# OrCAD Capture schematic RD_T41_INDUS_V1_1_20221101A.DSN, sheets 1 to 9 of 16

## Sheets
1 PAGE10_SLCD_BT656: size A3; title: RD_T41QFN_INDUS; rev: 1.1; note: SLCD_BT656
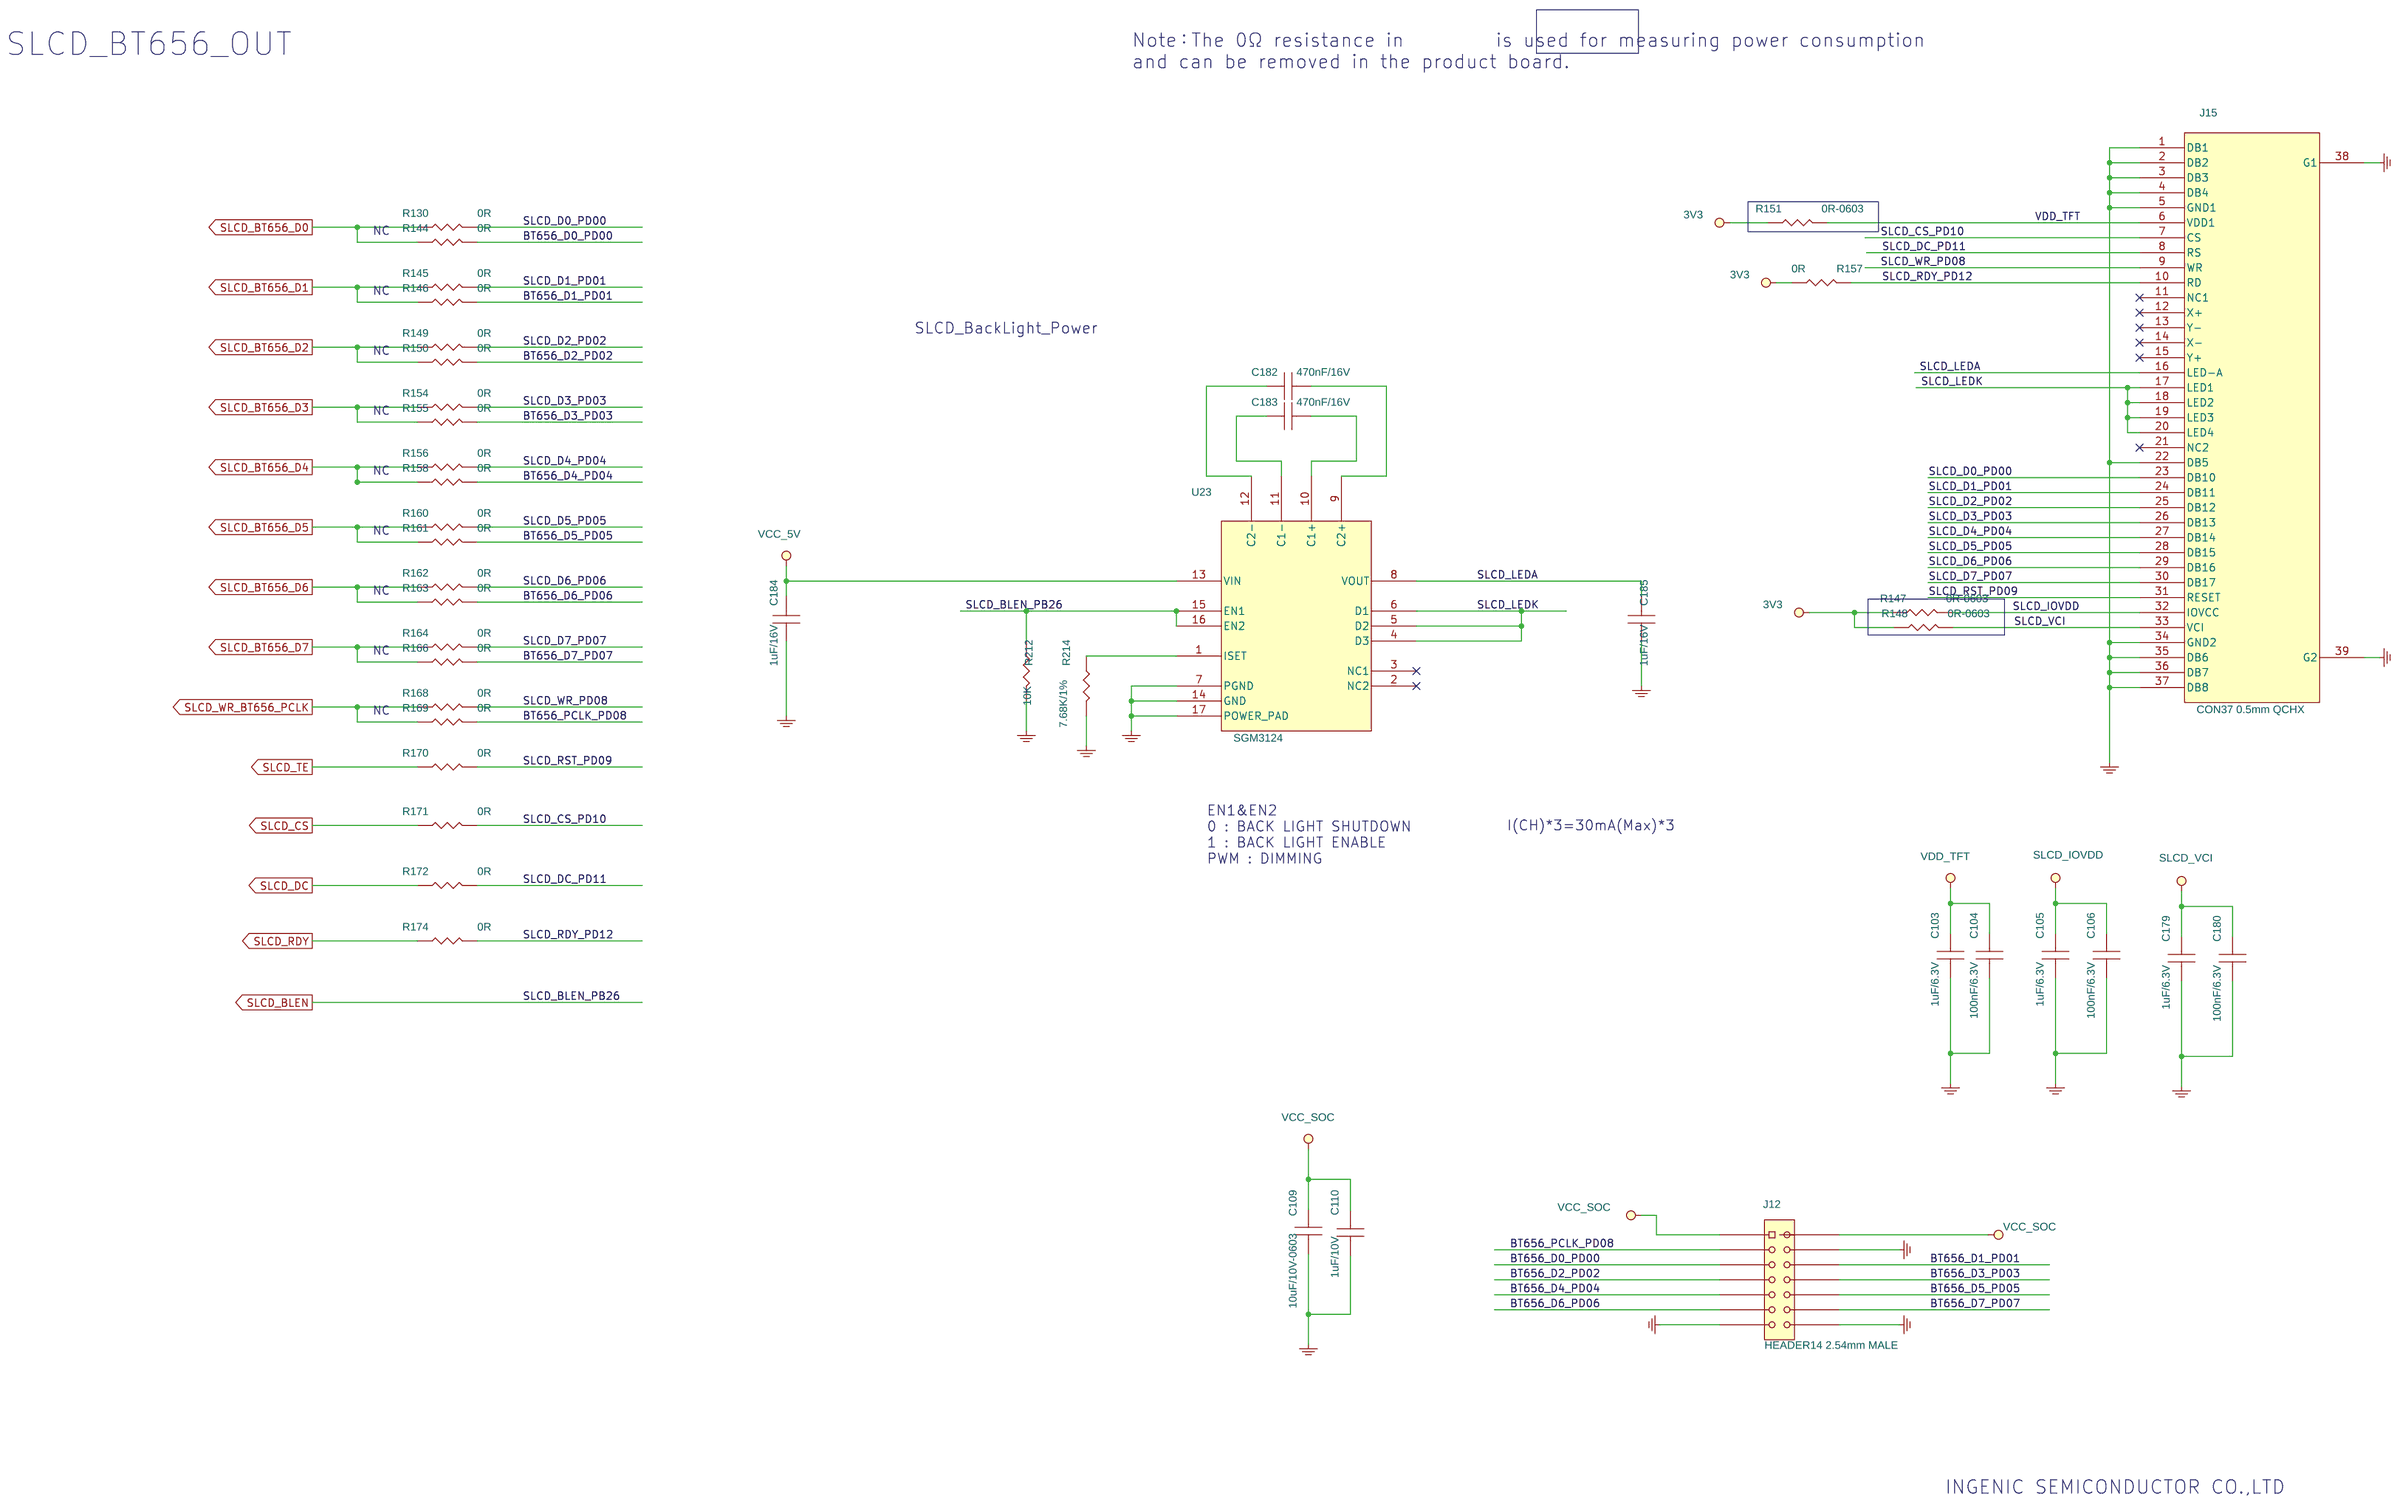
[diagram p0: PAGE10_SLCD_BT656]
2 PAGE13_ETH_PHY: size A3; note: ETH_PHY
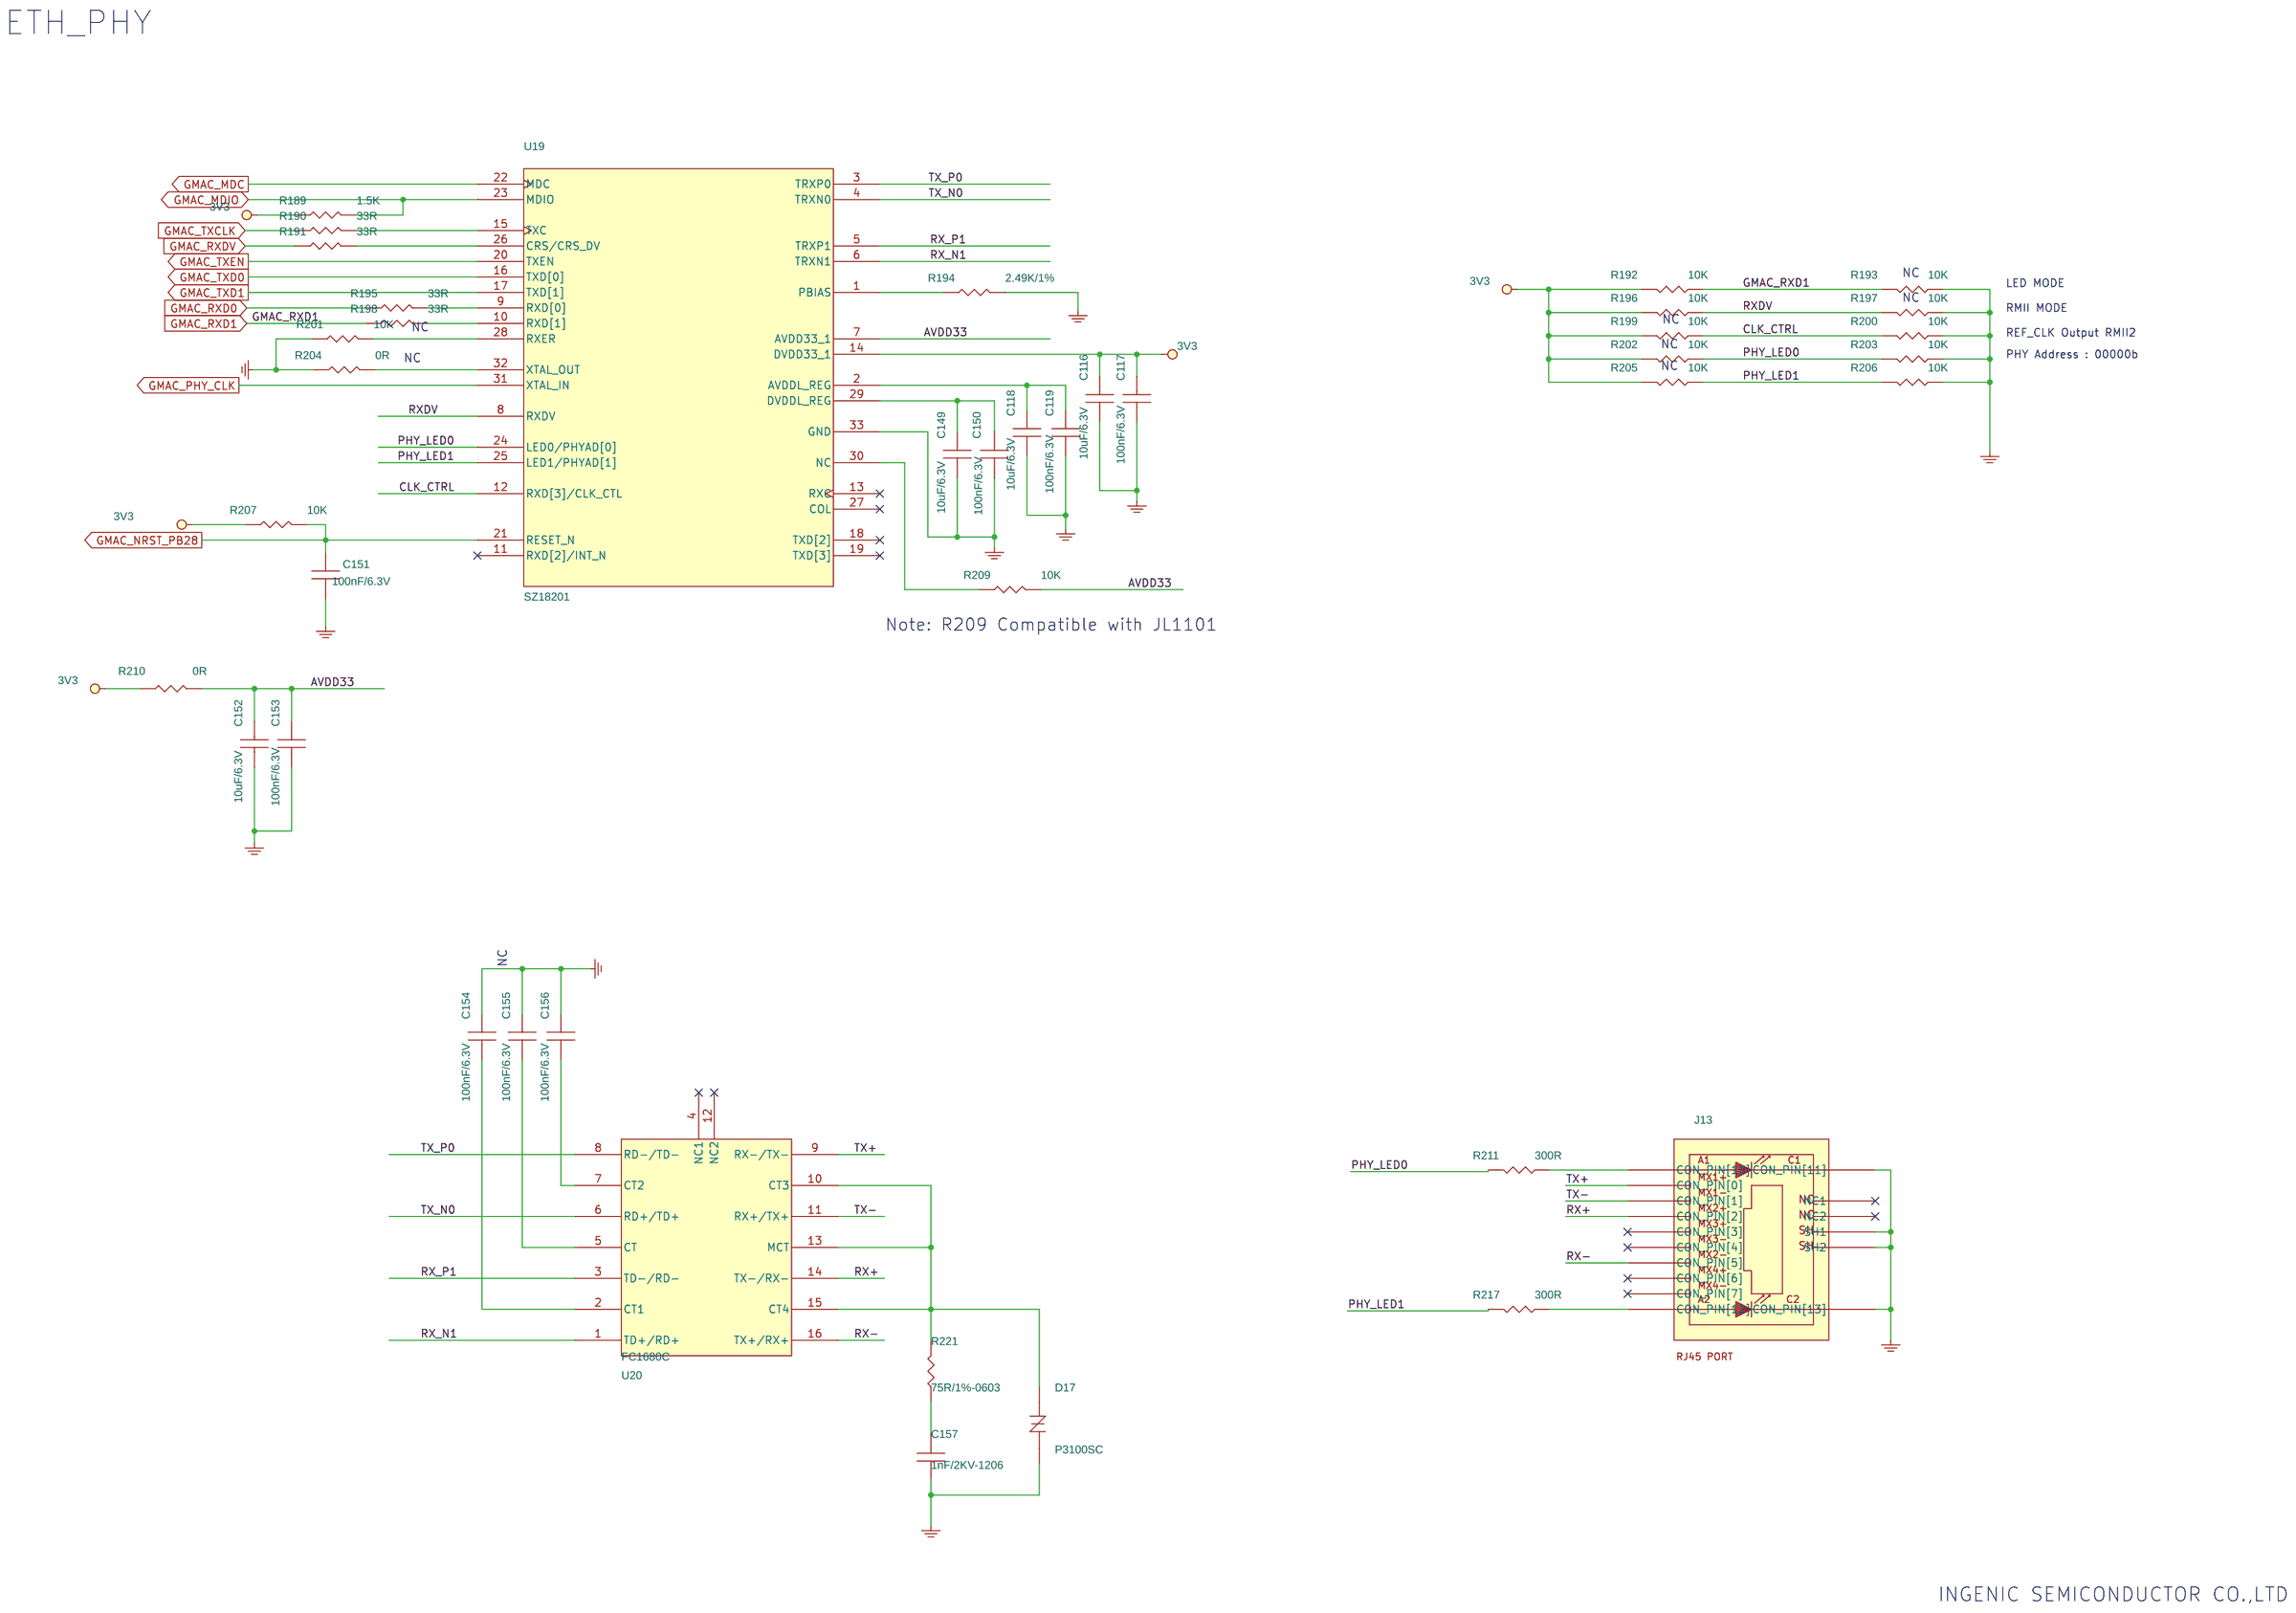
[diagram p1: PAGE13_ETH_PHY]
3 PAGE12_WIFI_MOUDLE: size A3; note: WIFI_ATBM6441
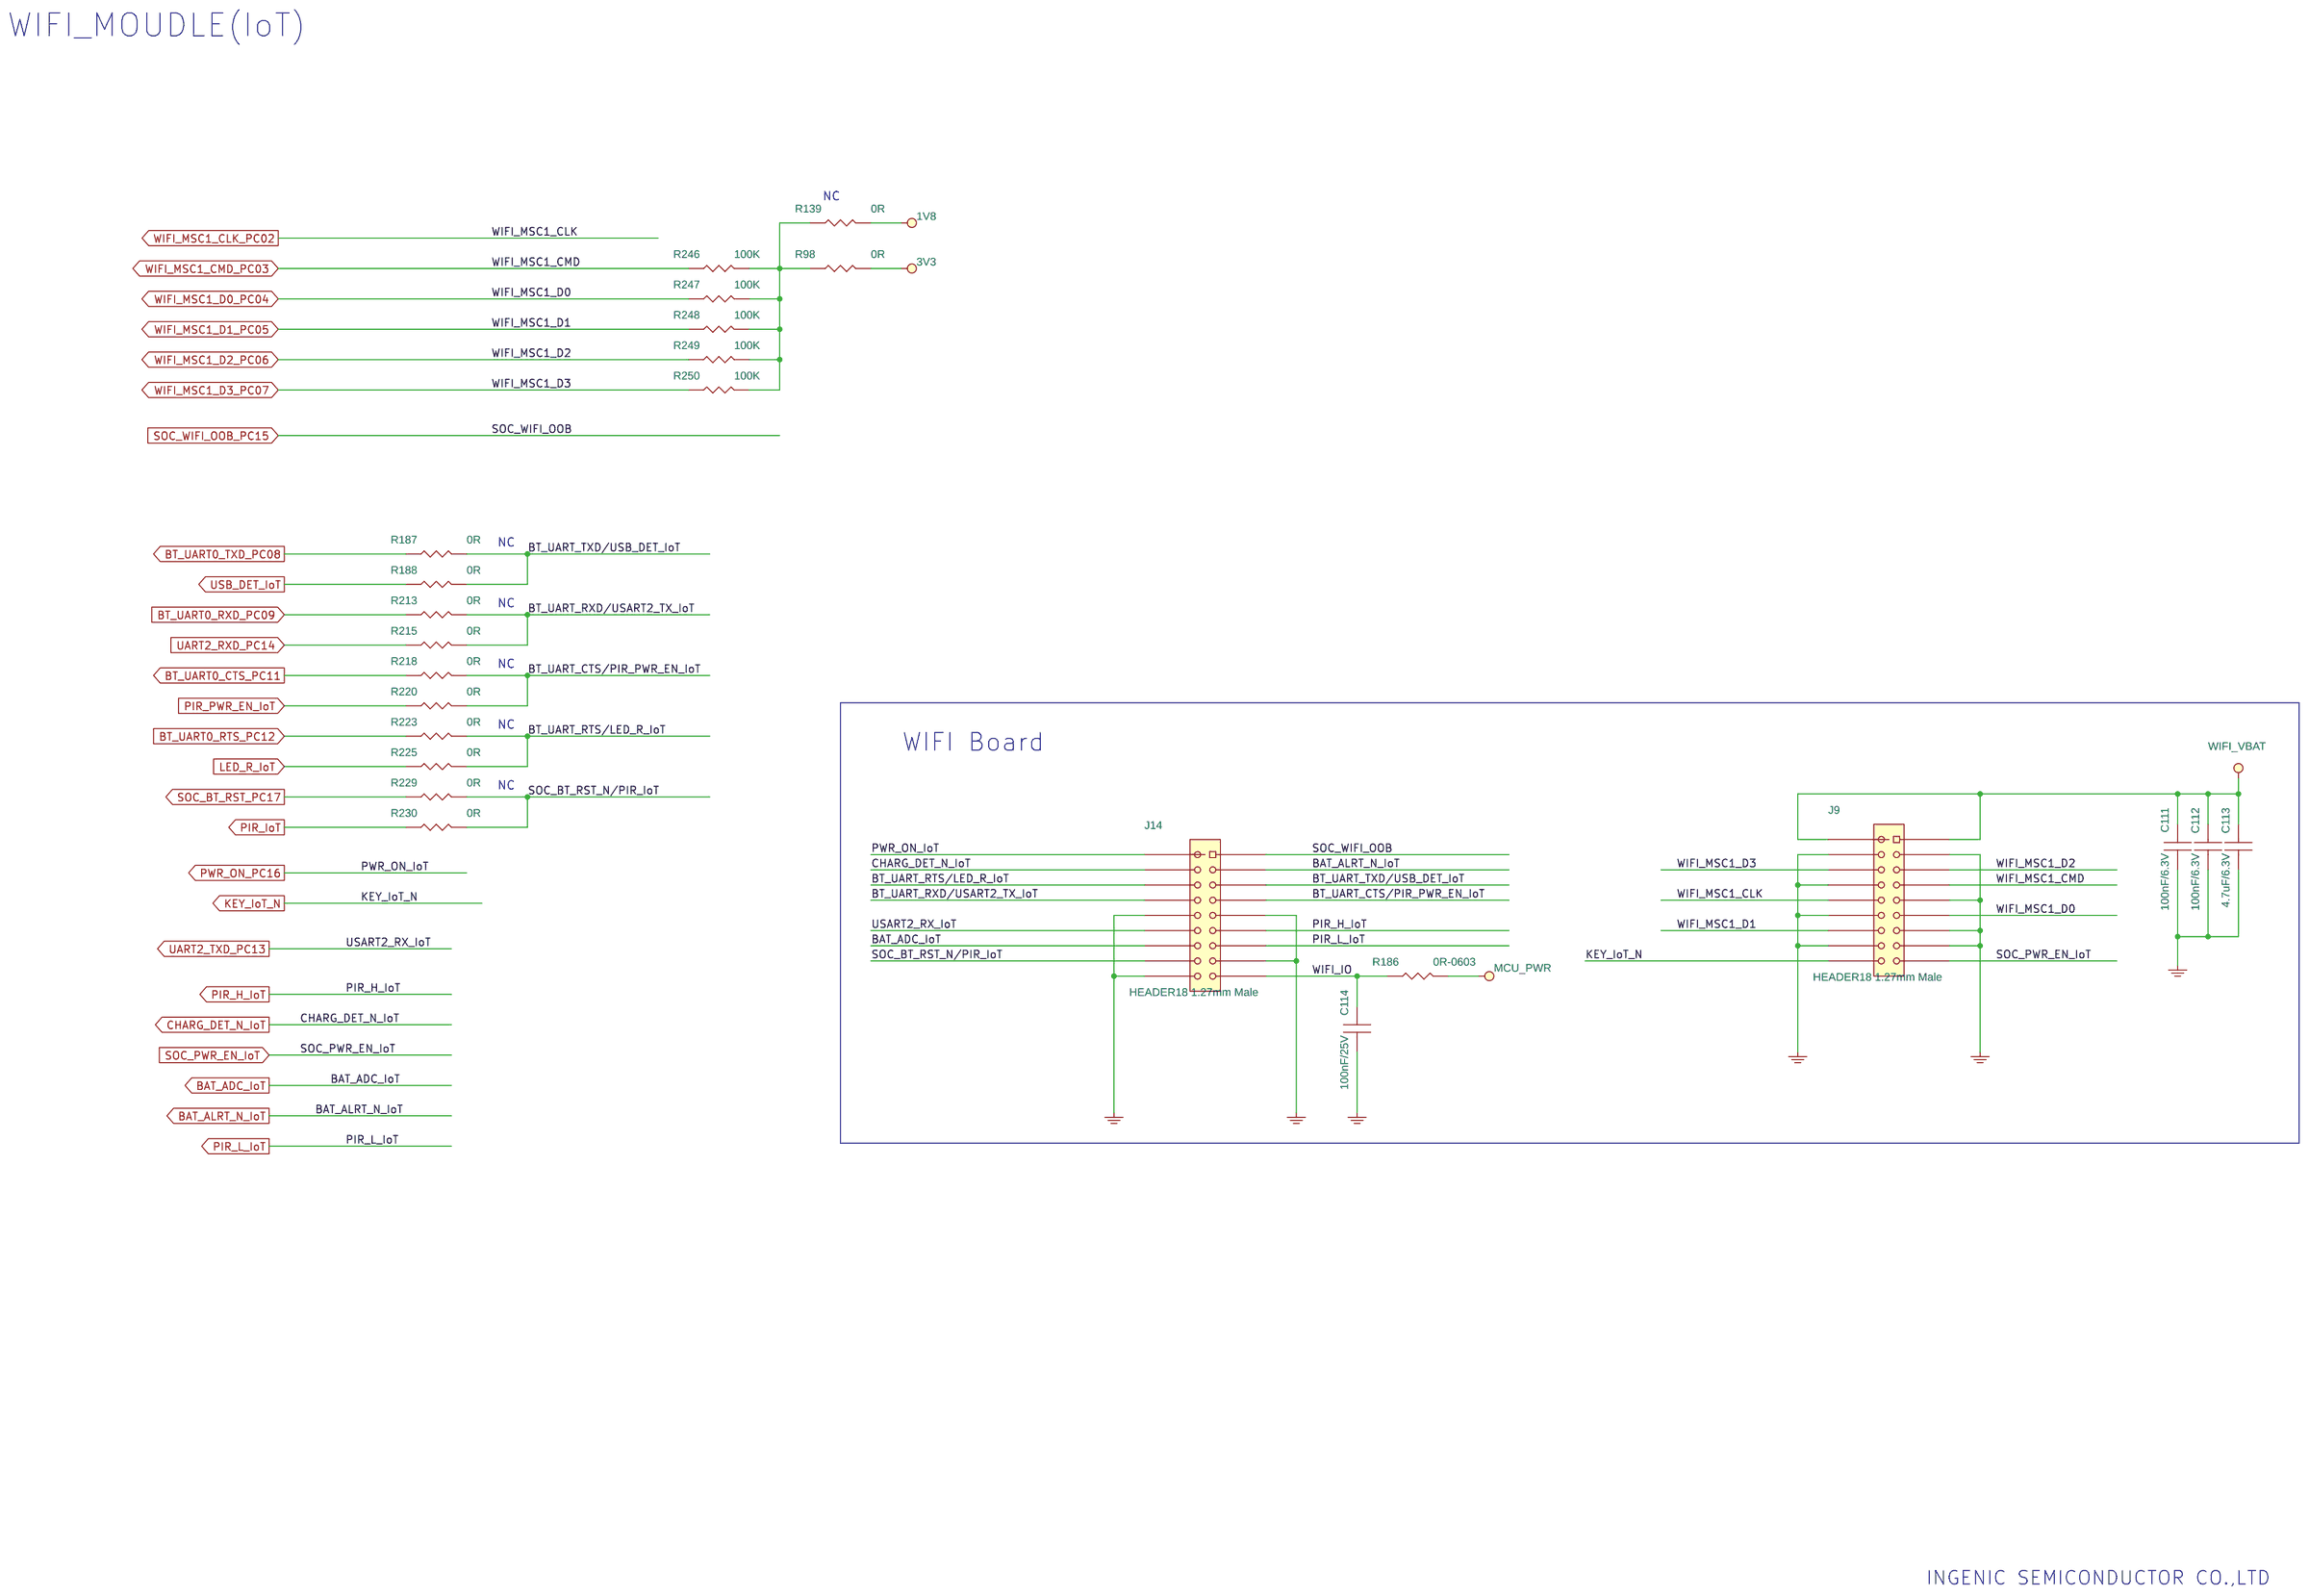
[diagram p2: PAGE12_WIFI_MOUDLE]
4 PAGE08_T41_INTERFACE02: size A3; note: T41_INTERFACE02
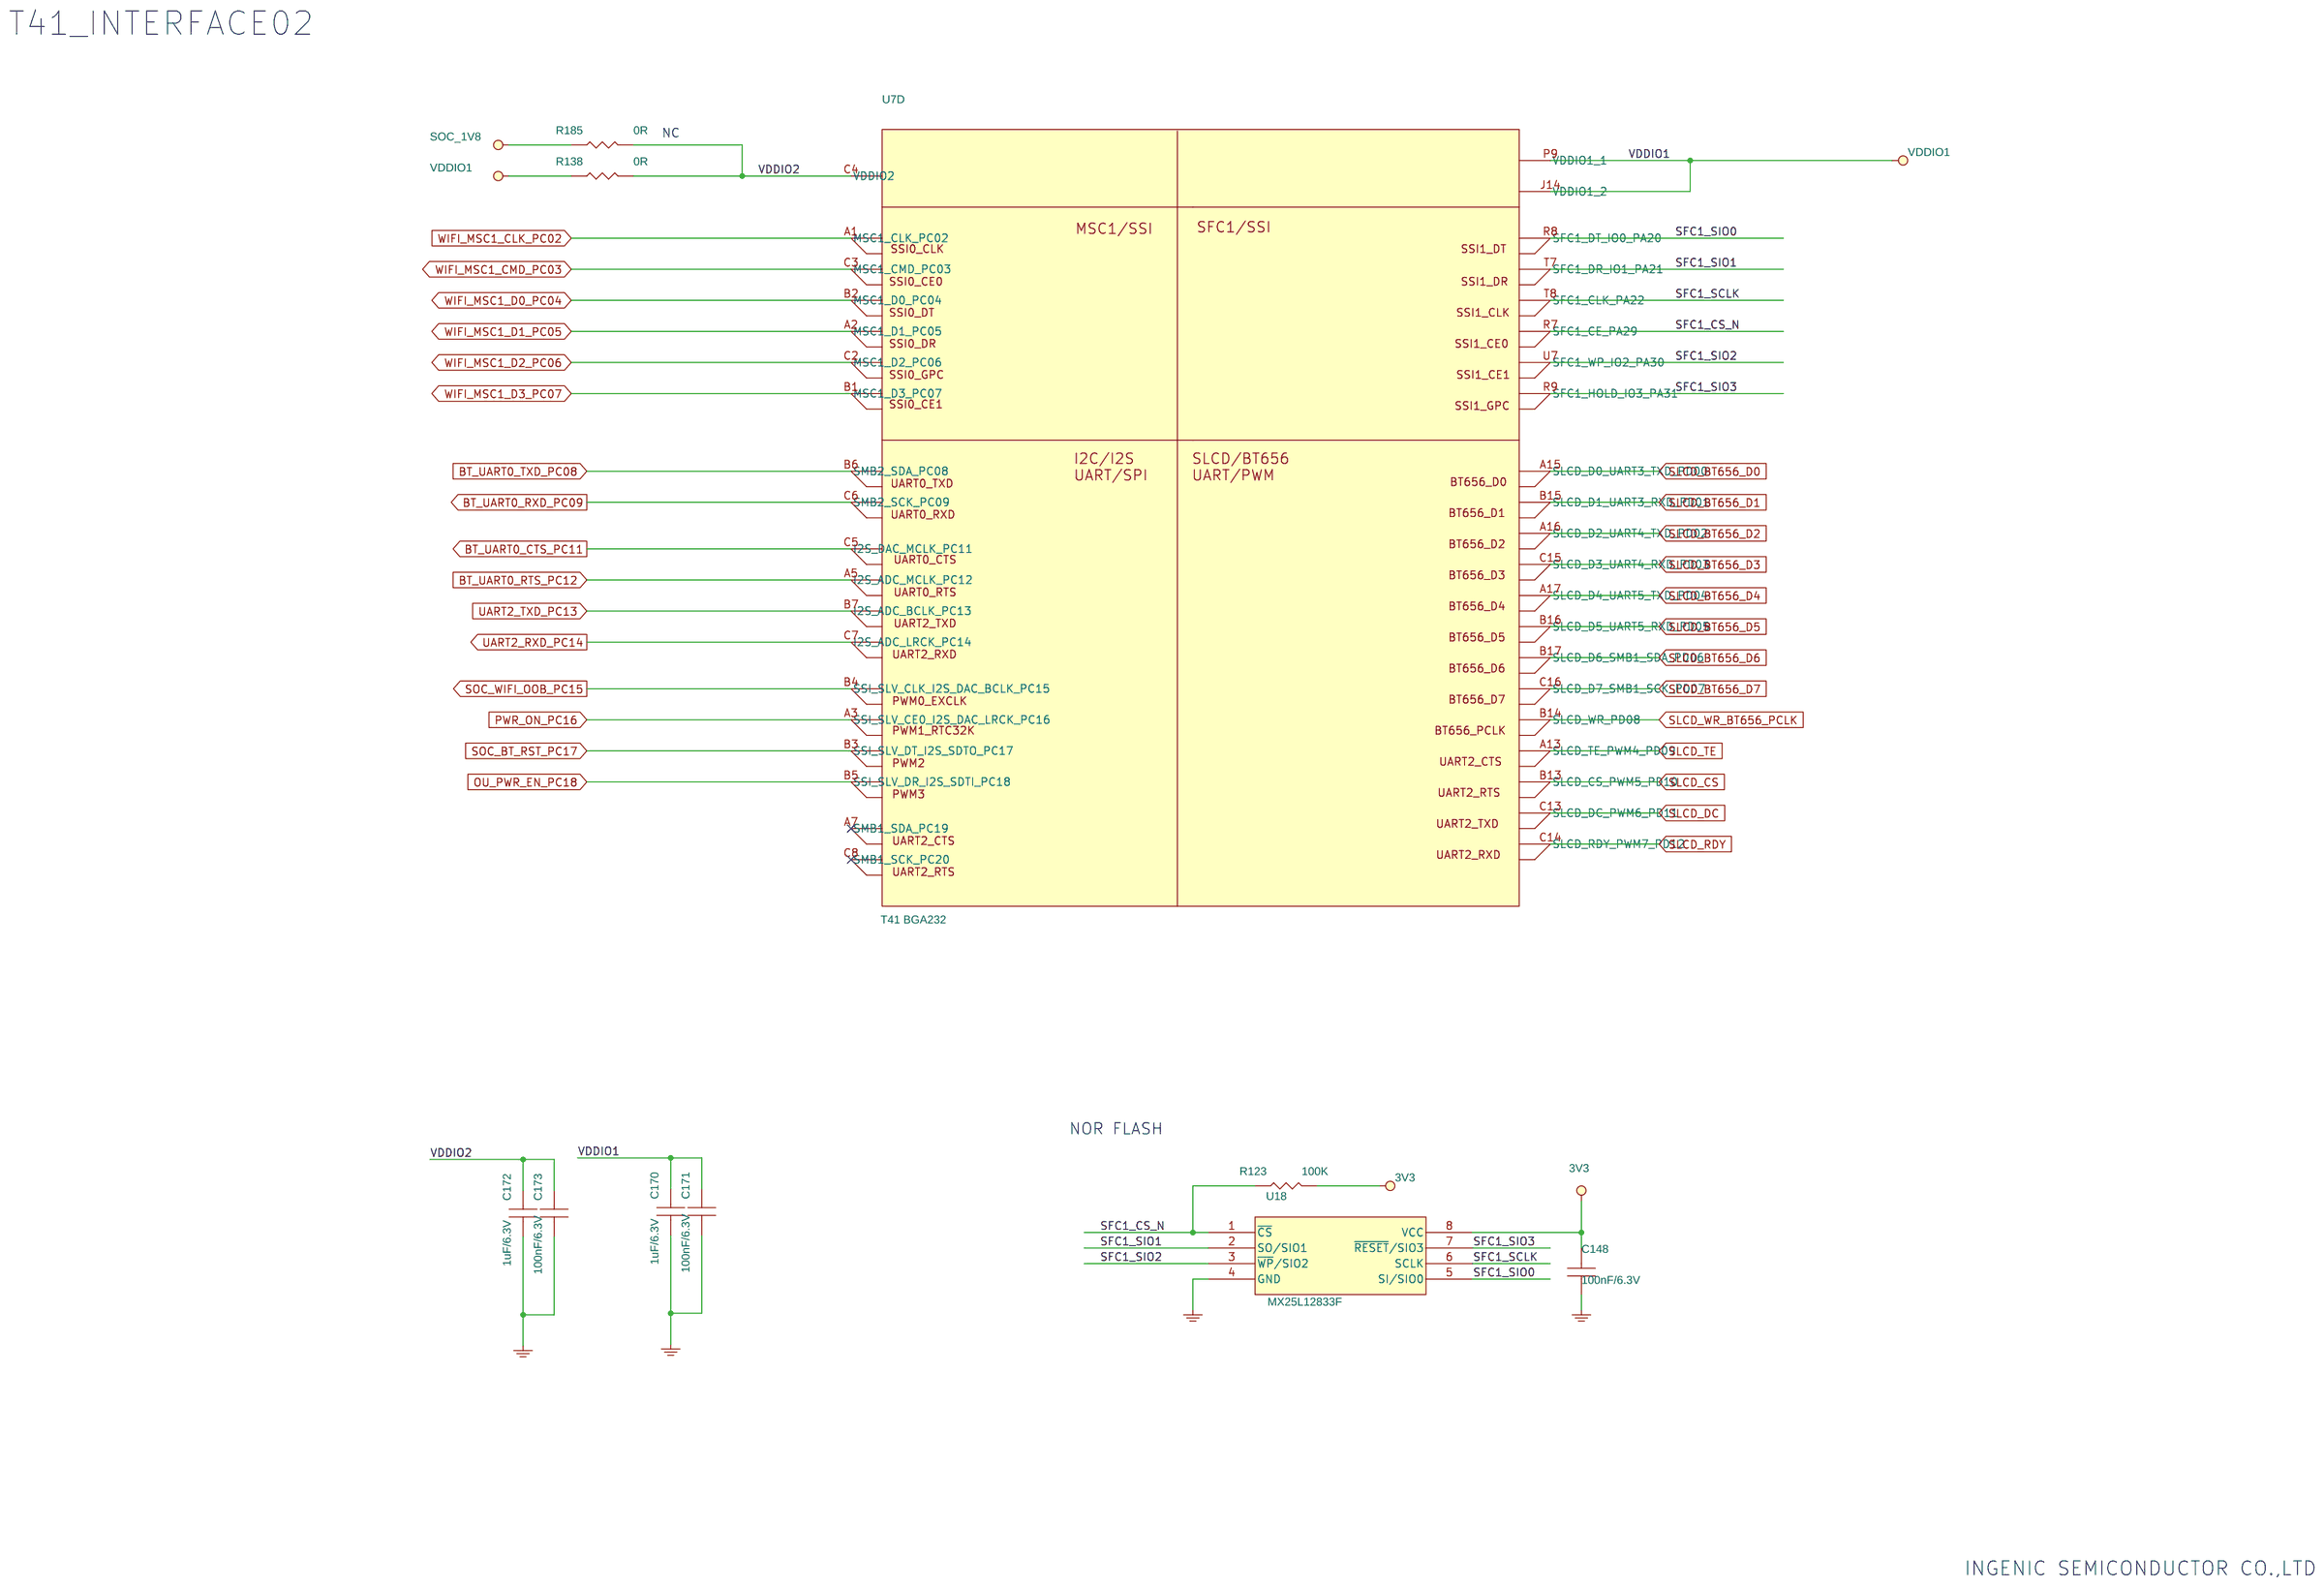
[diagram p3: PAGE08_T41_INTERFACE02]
5 PAGE07_T41_INTERFACE01: size A3; note: T41_INTERFACE01
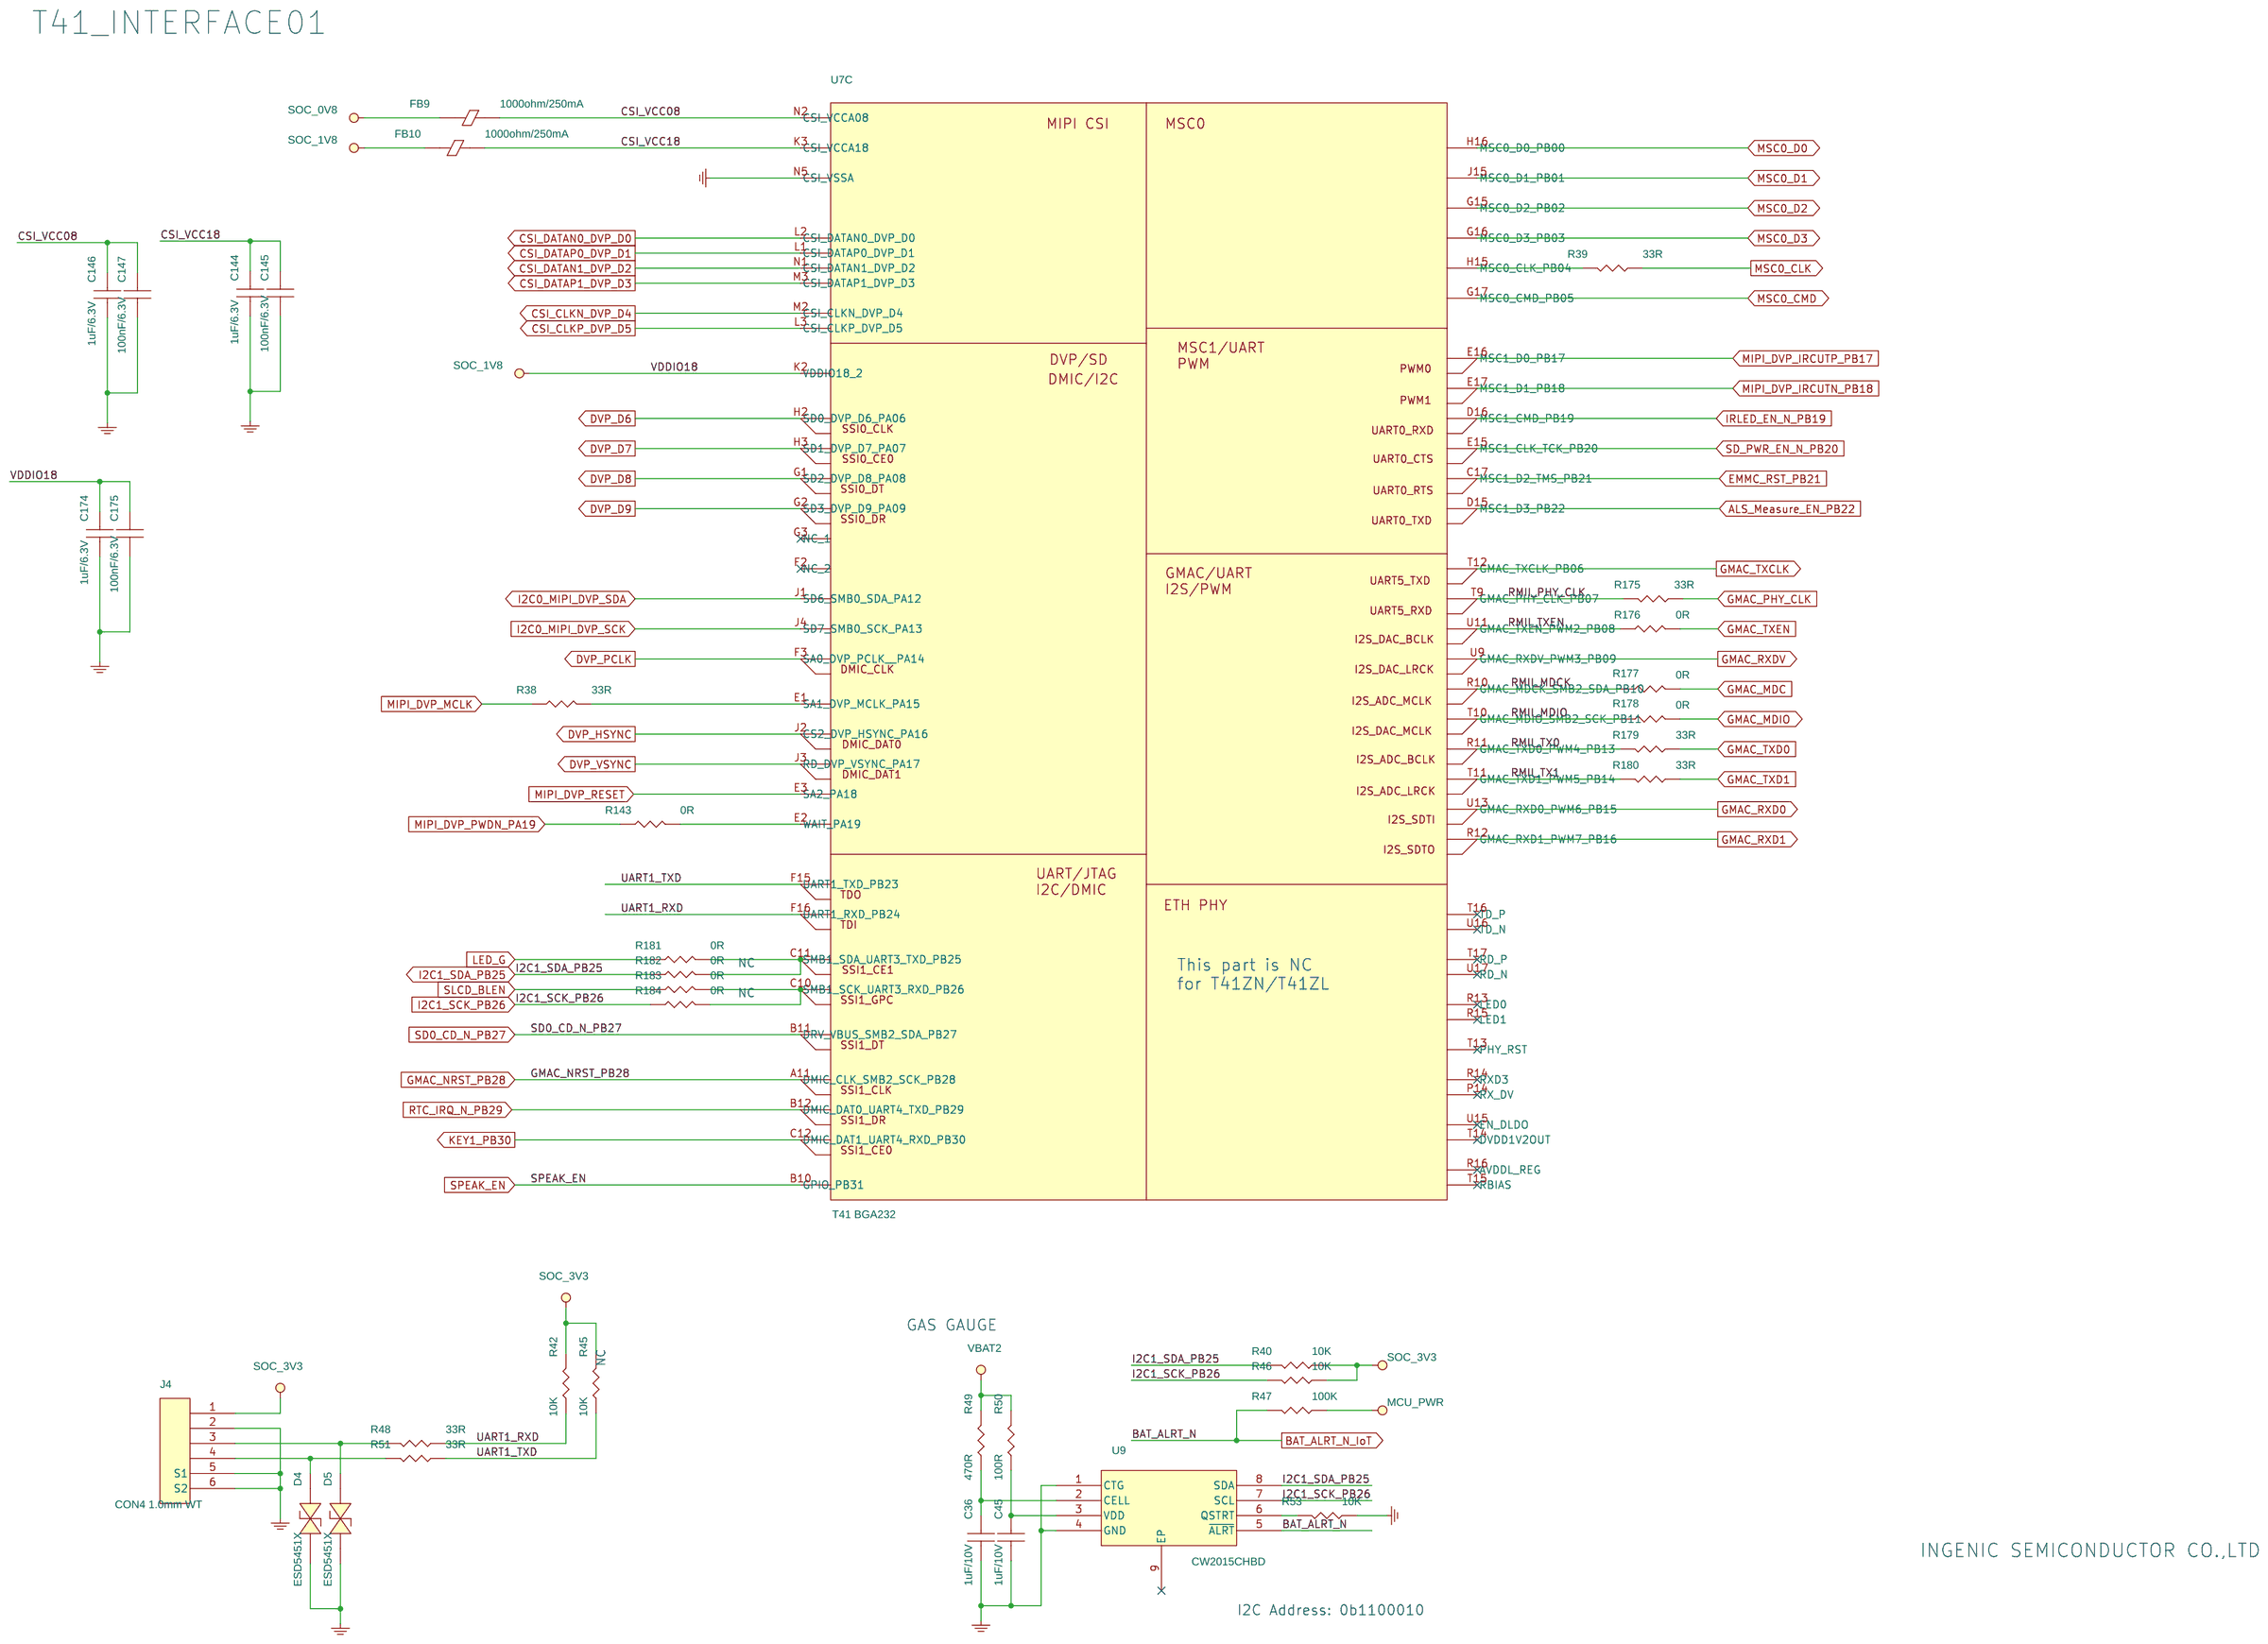
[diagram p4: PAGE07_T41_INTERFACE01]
6 PAGE14_PIR_LDR: size A3; note: PIR_LDR
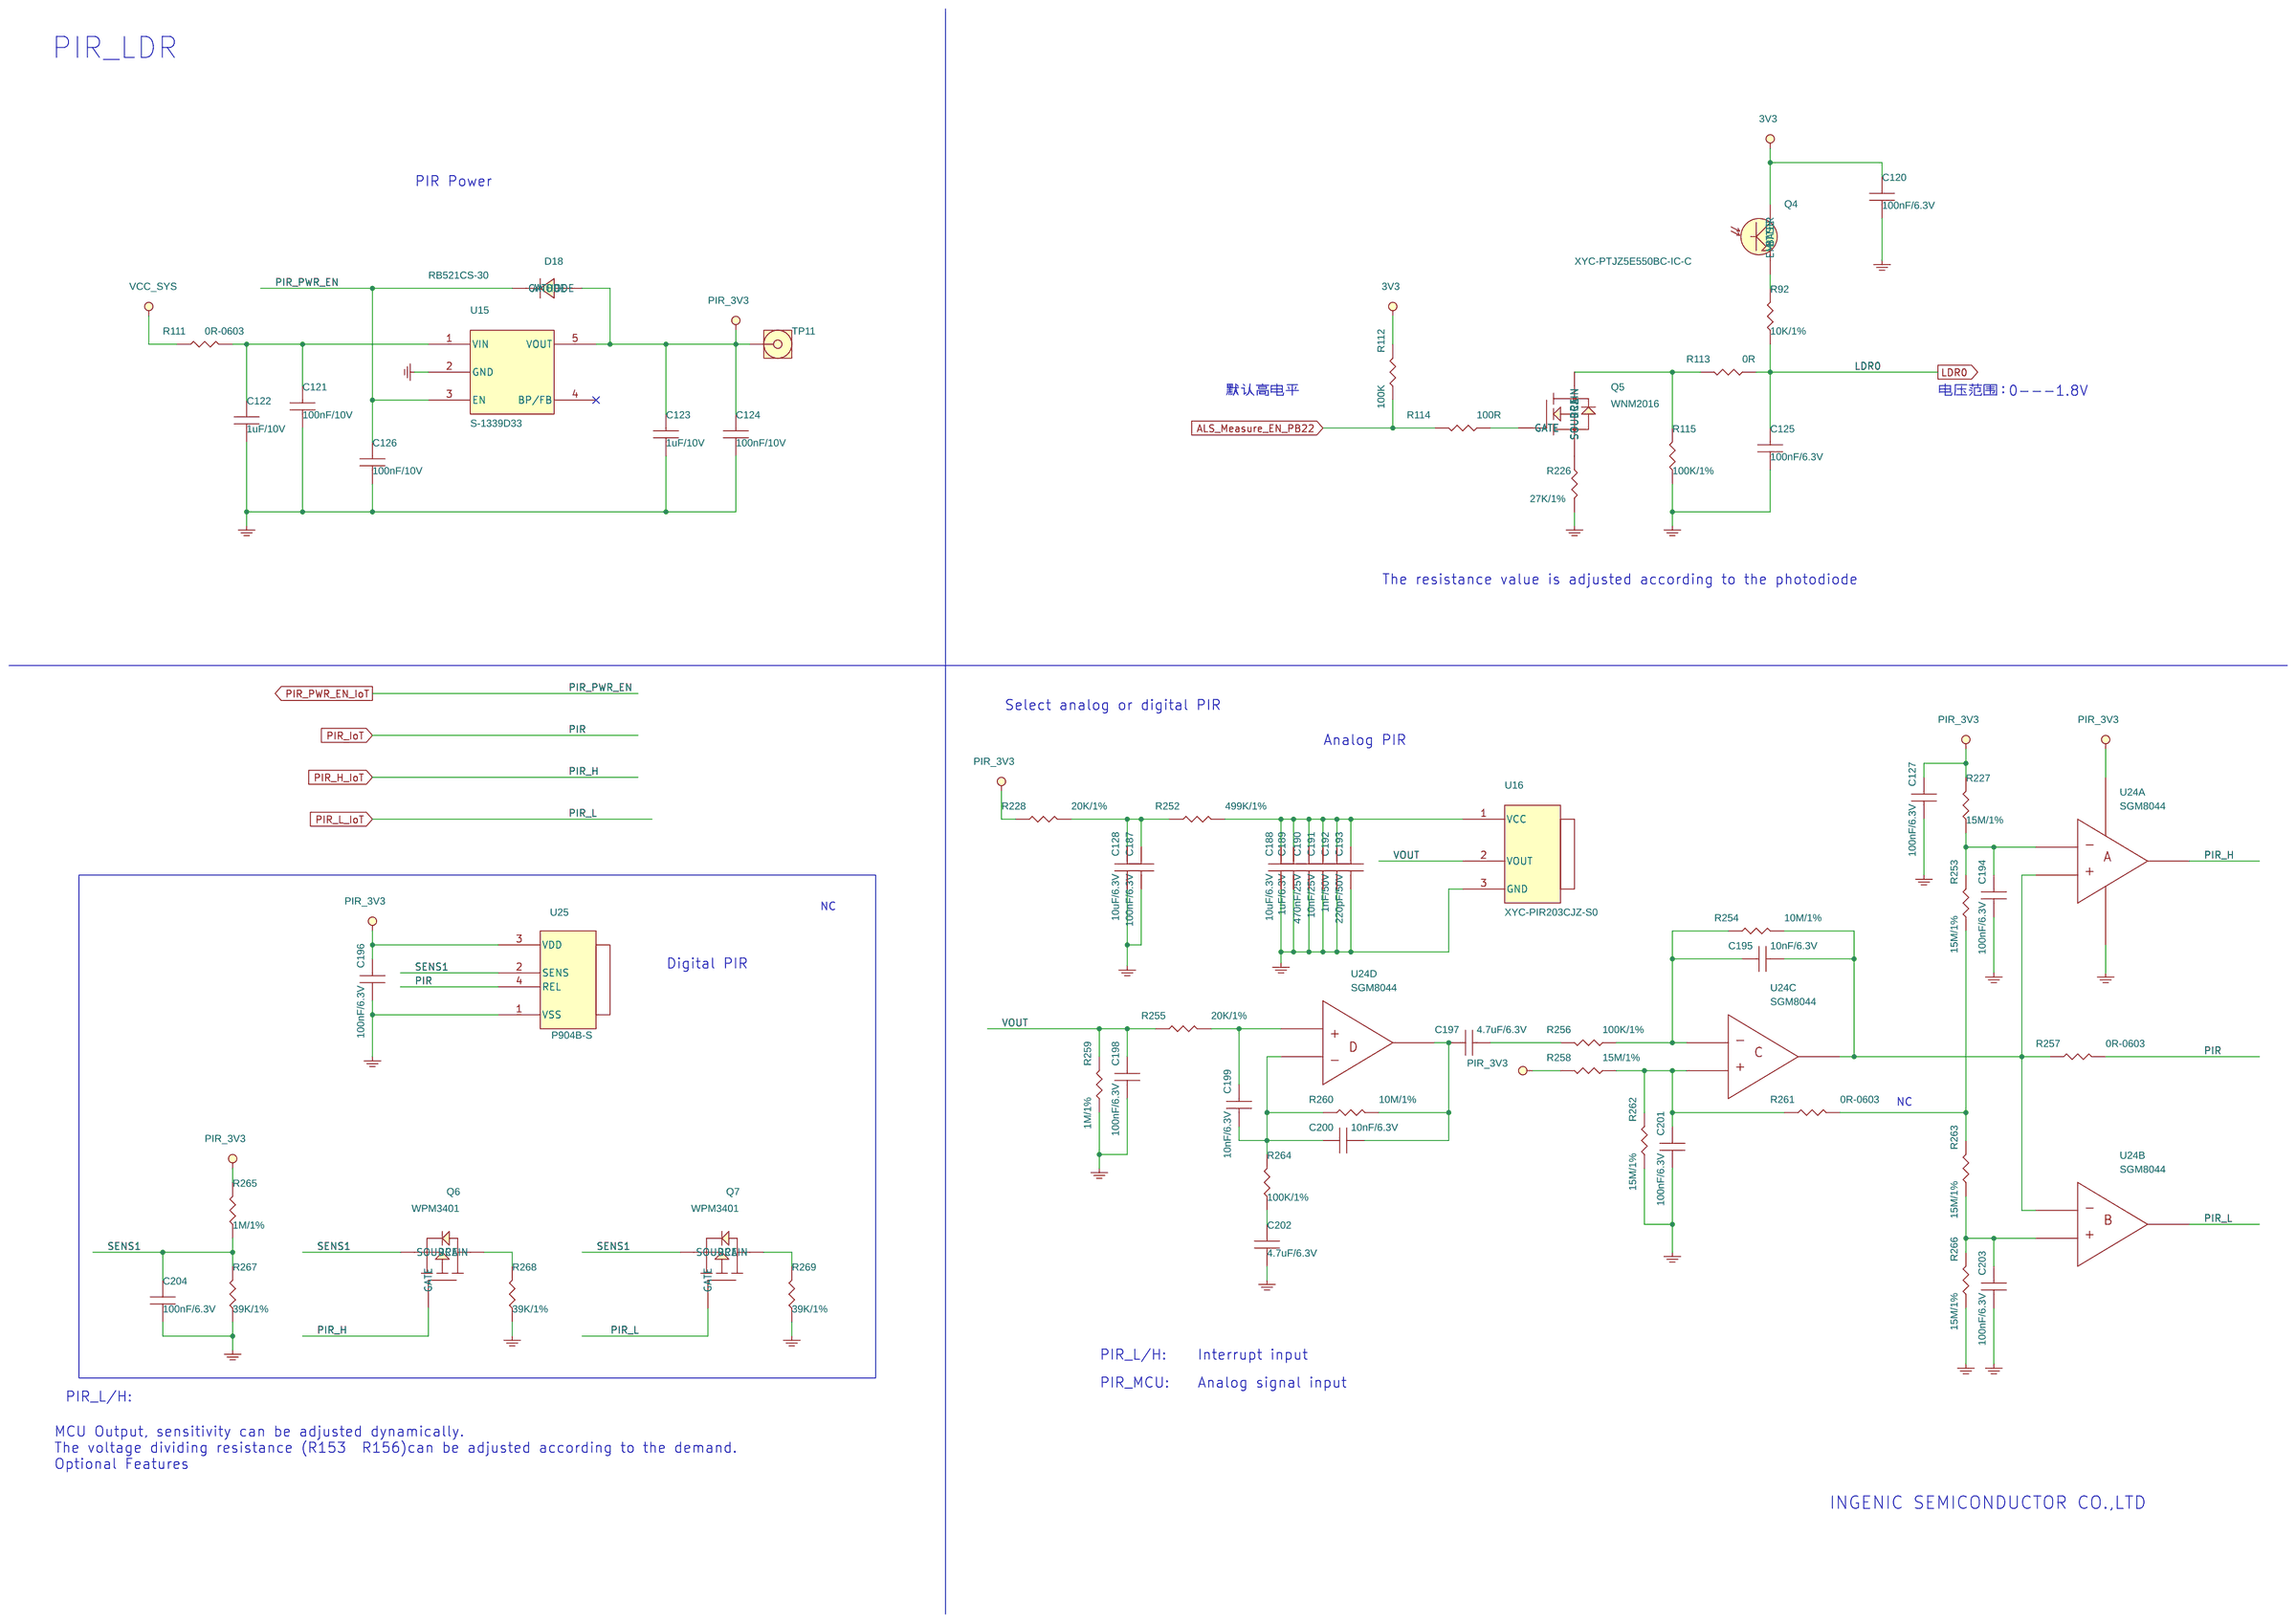
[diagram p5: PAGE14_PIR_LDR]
7 PAGE01_COVER: note: COVER
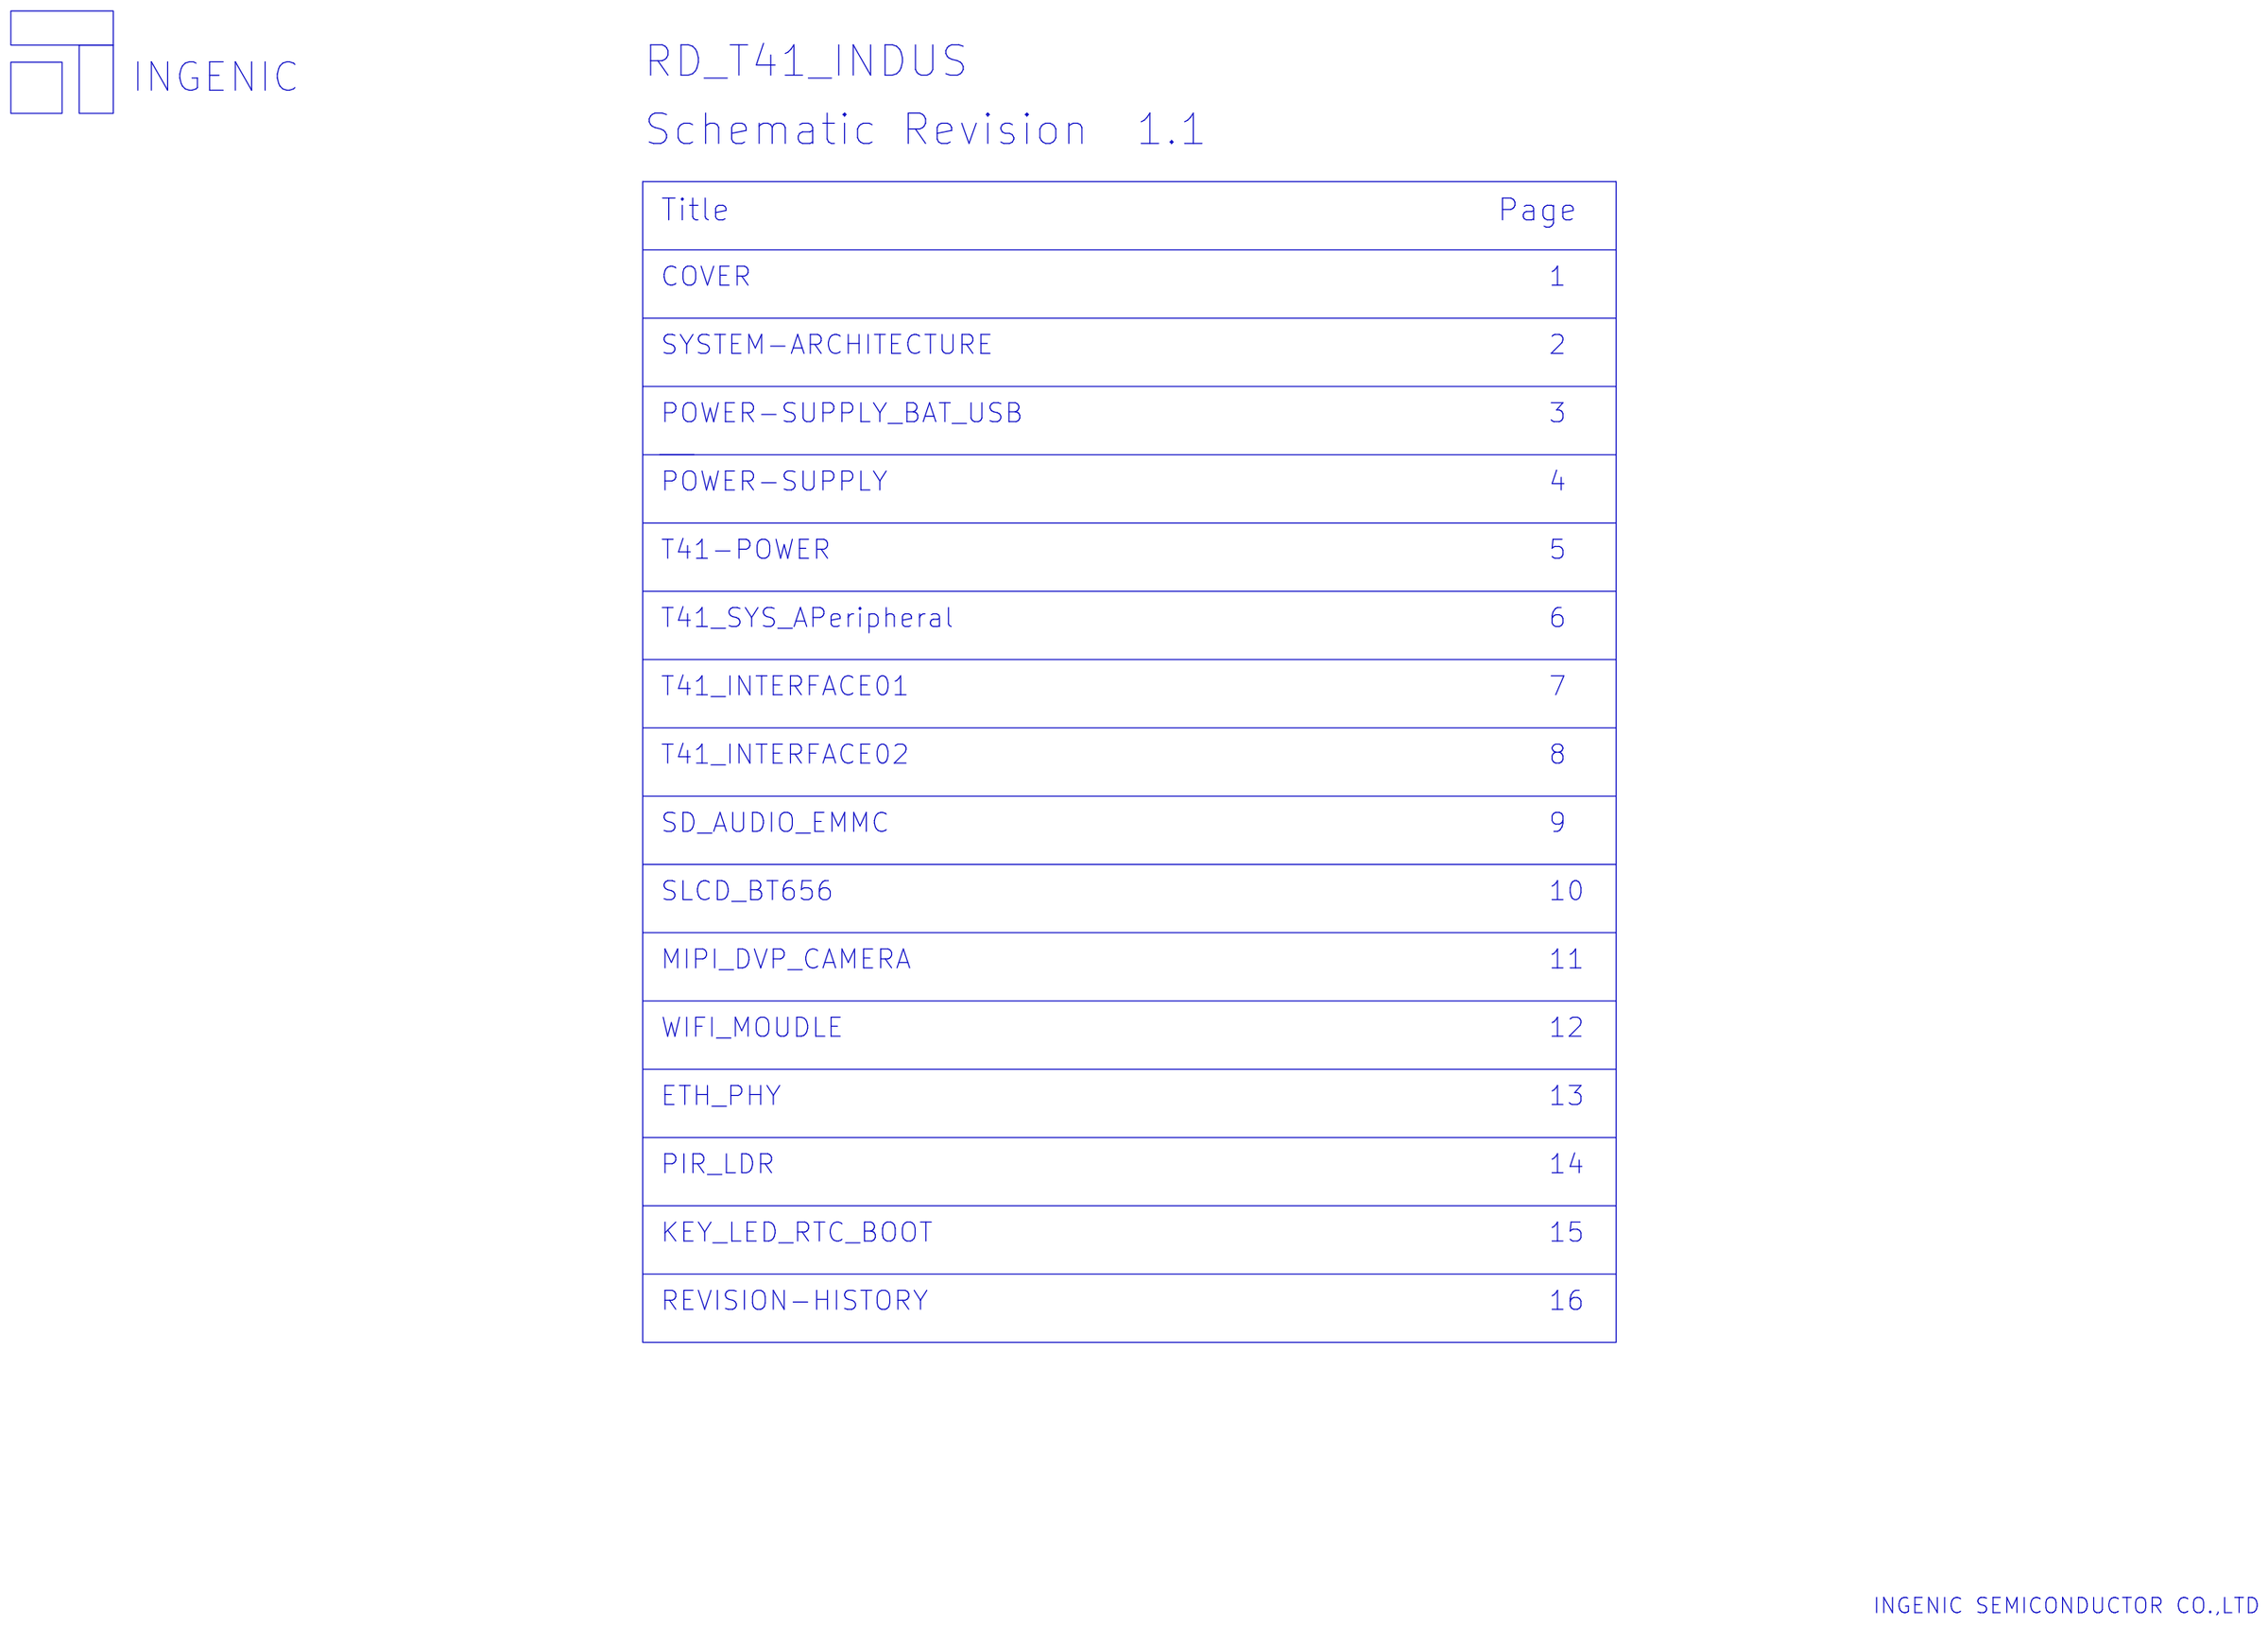
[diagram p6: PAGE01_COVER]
8 PAGE02_SYSTEM-ARCHITECT: note: SYSTEM-ARCHITECTURE
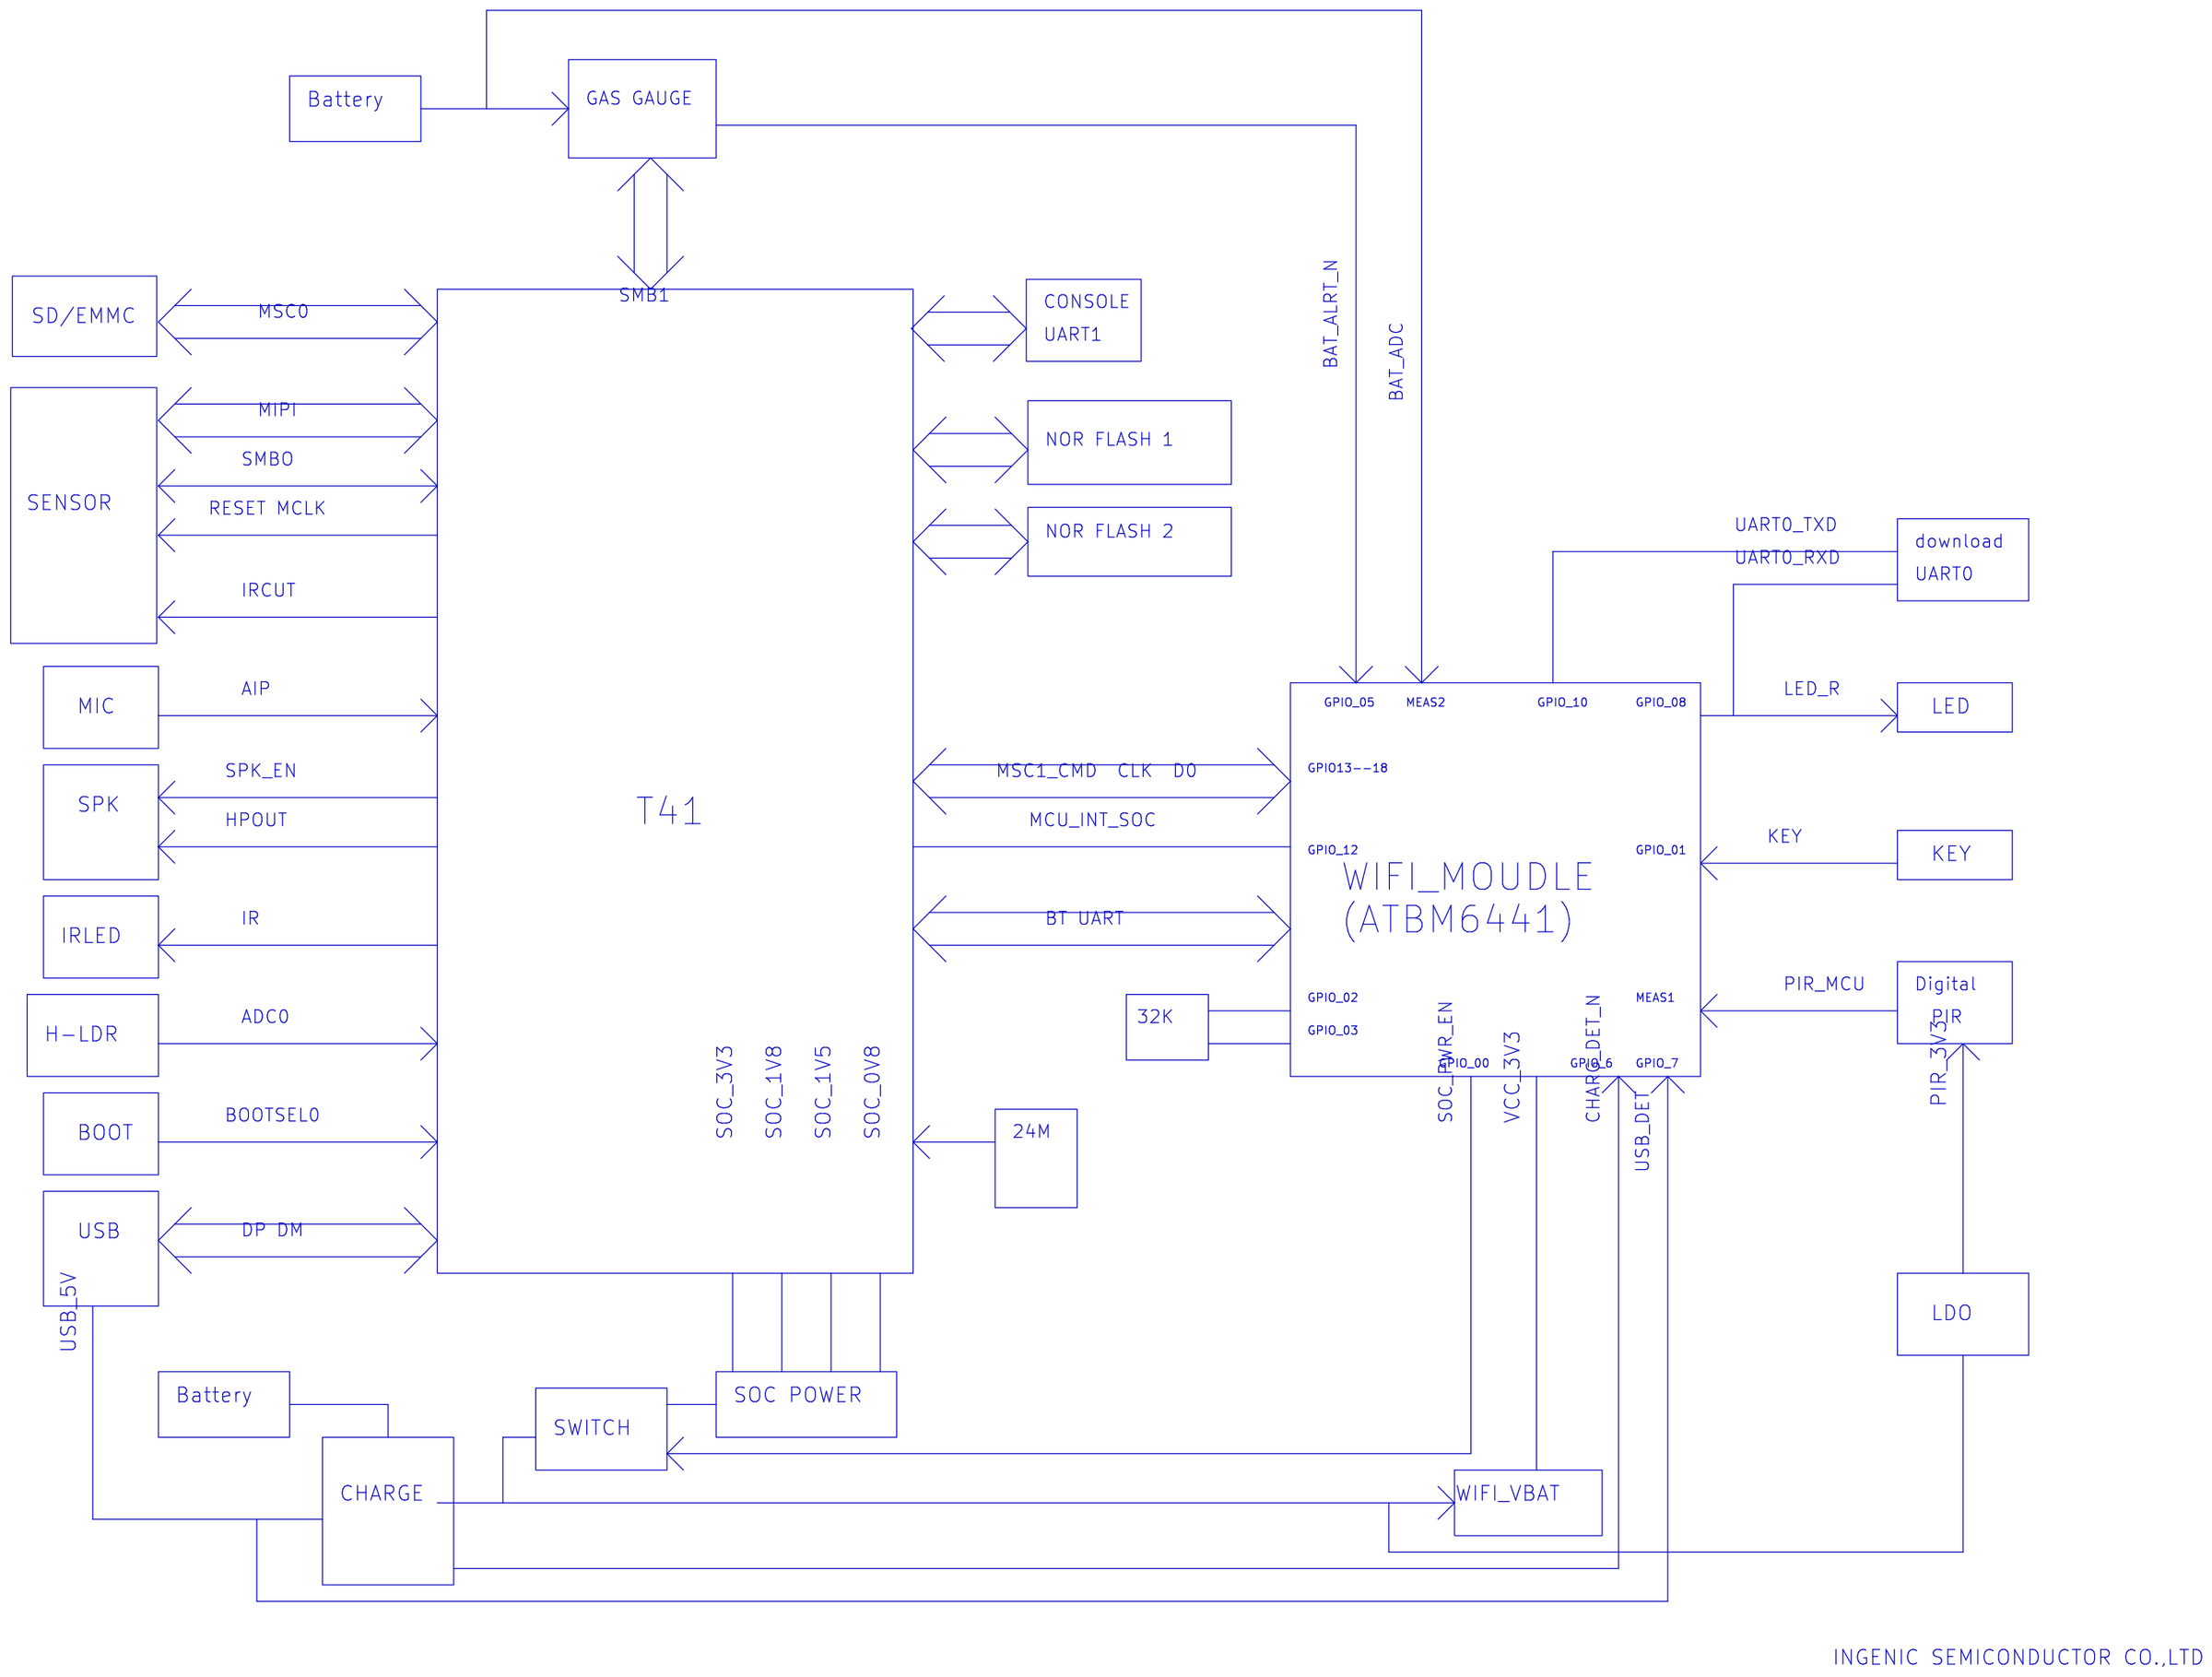
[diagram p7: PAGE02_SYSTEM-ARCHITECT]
9 PAGE03_POWER-SUPPLY_BAT_USB: size A3; note: POWER-SUPPLY_BAT_USB
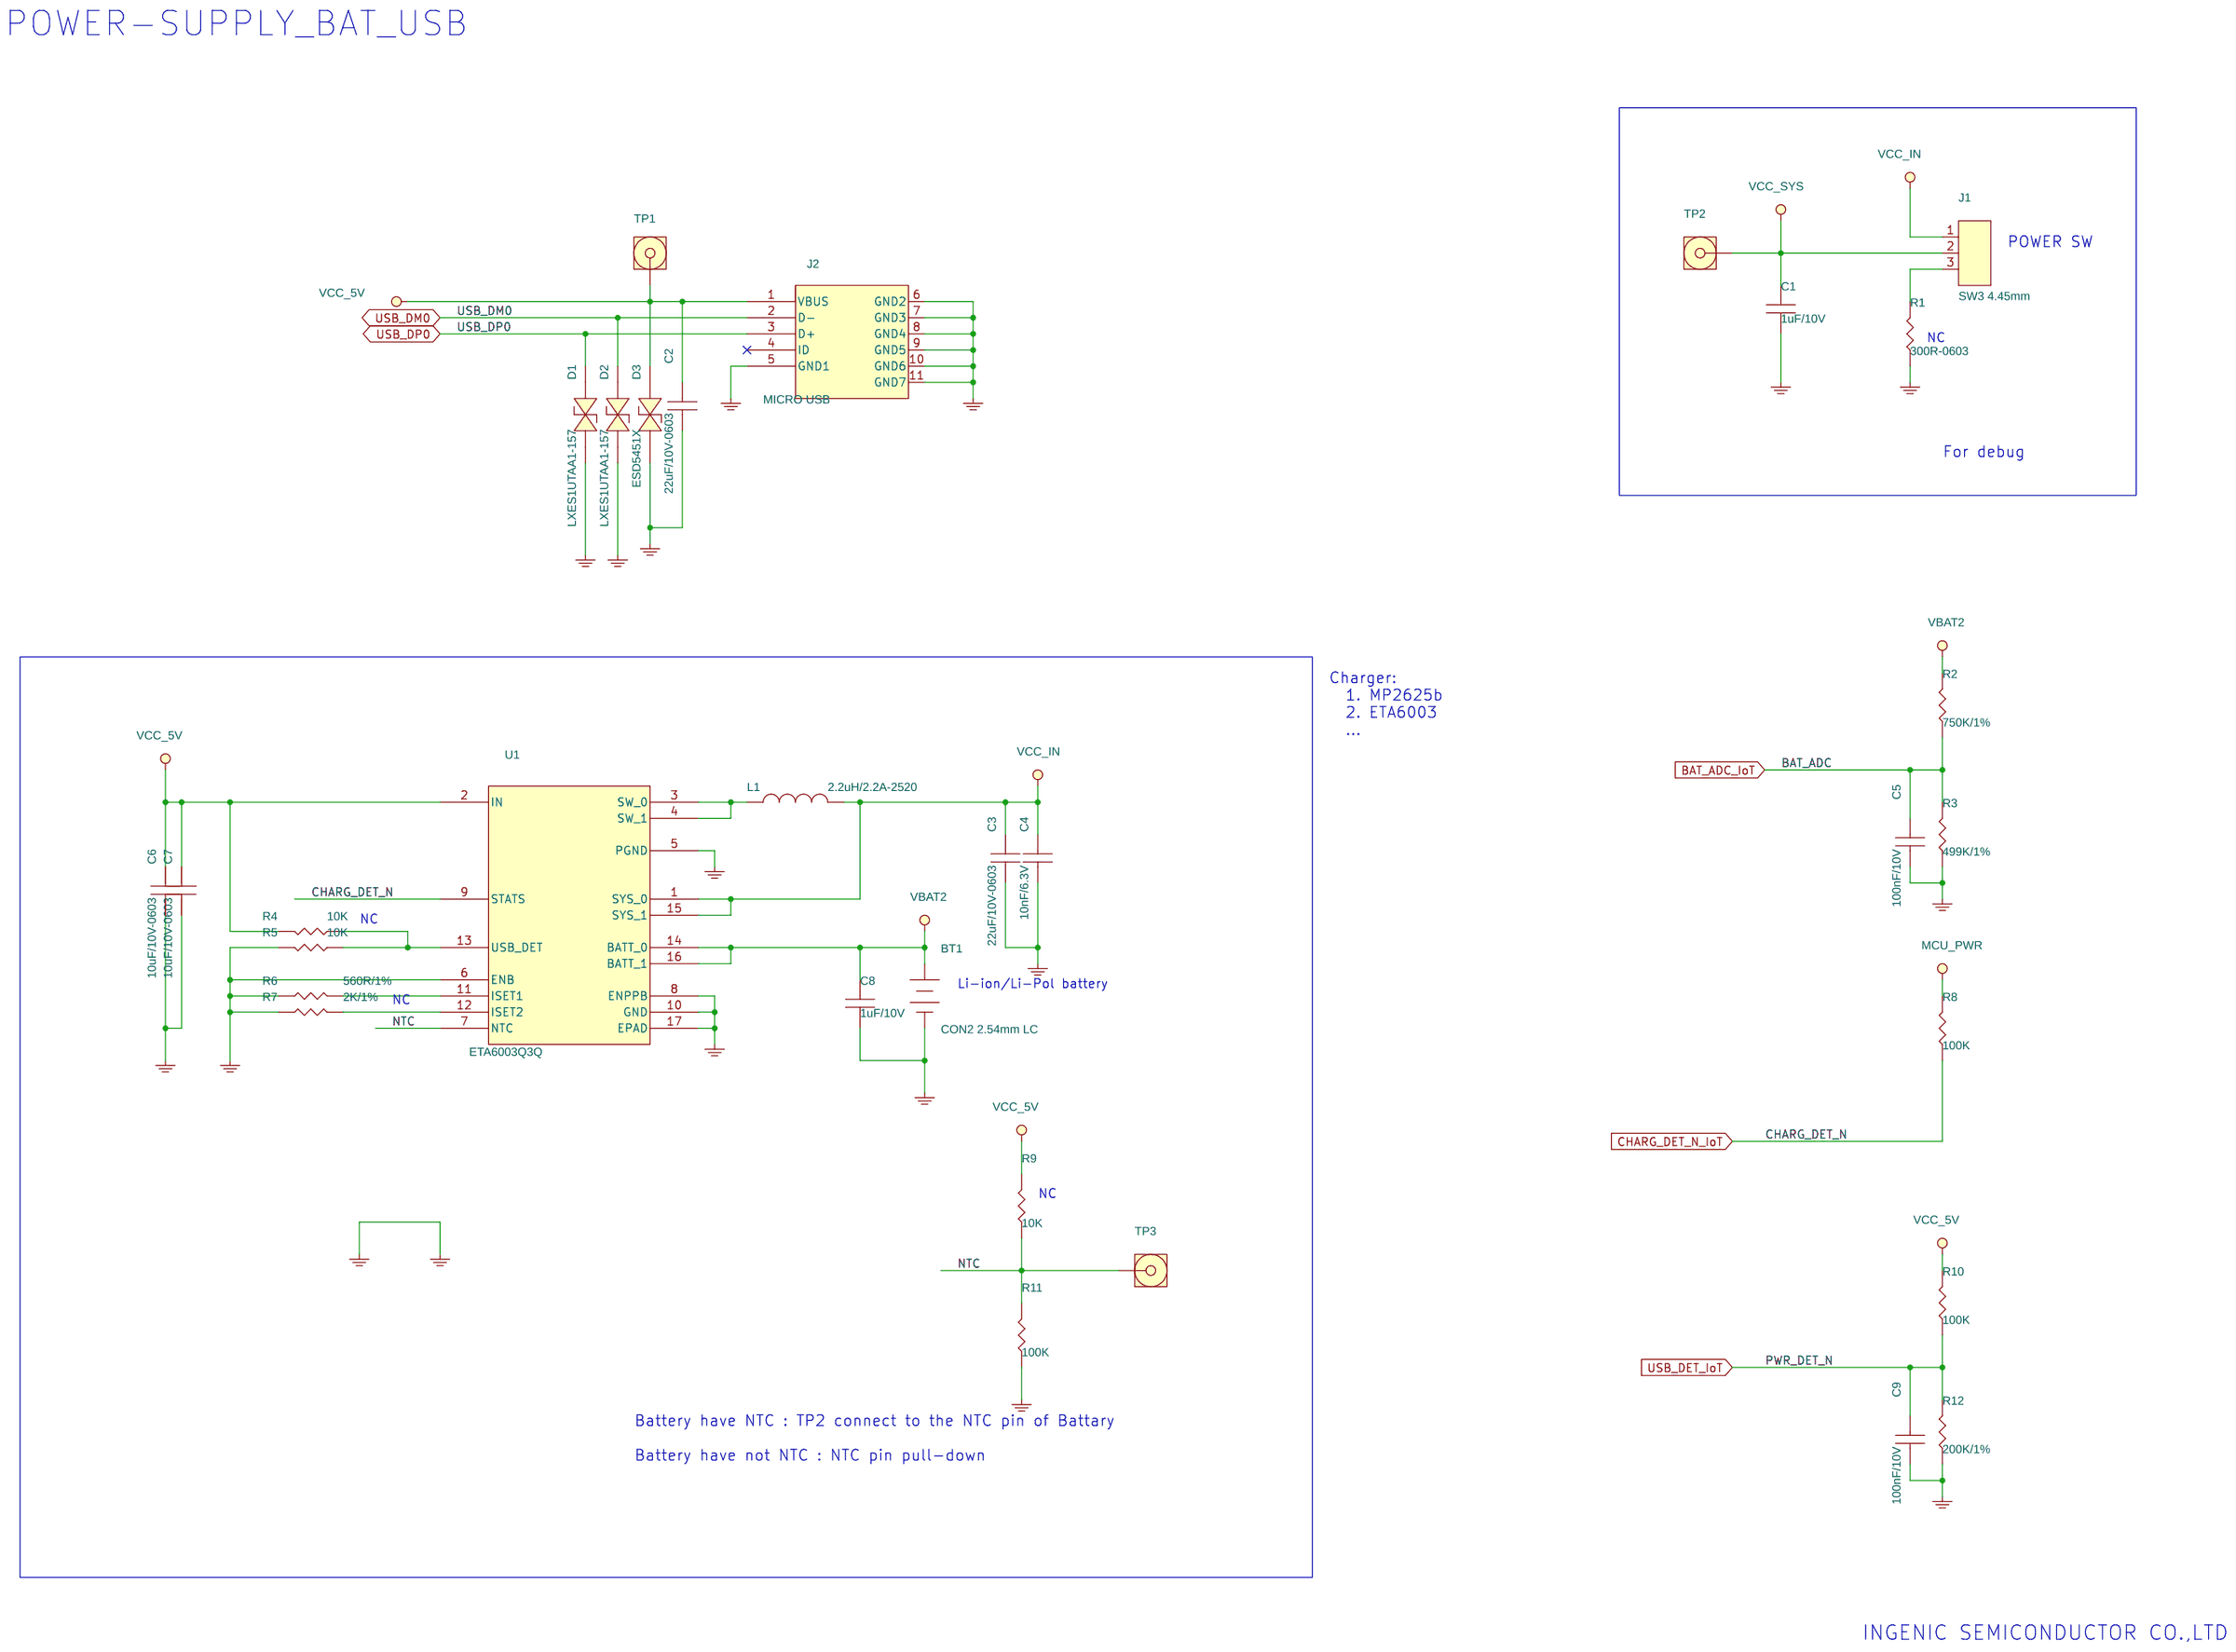
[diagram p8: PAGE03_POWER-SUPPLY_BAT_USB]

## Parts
sheet PAGE03_POWER-SUPPLY_BAT_USB
BT1  CON2 2.54mm LC  [CON2-2D54-LC]
C1  1uF/10V  [C0402]
C2  22uF/10V-0603  [C0603]
C3  22uF/10V-0603  [C0603]
C4  10nF/6.3V  [C0402]
C5  100nF/10V  [C0402]
C6  10uF/10V-0603  [C0603]
C7  10uF/10V-0603  [C0603]
C8  1uF/10V  [C0402]
C9  100nF/10V  [C0402]
D1  LXES1UTAA1-157  [DFN1006]
D2  LXES1UTAA1-157  [DFN1006]
D3  ESD5451X  [ESD0402]
J1  SW3 4.45mm  [PSW_3P]
J2  MICRO USB  [MICROUSB_B_NJ5P]
L1  2.2uH/2.2A-2520  [L2520]
R1  300R-0603  [R0603]
R2  750K/1%  [R0402]
R3  499K/1%  [R0402]
R4  10K  [R0402]
R5  10K  [R0402]
R6  560R/1%  [R0402]
R7  2K/1%  [R0402]
R8  100K  [R0402]
R9  10K  [R0402]
R10  100K  [R0402]
R11  100K  [R0402]
R12  200K/1%  [R0402]
TP1  D0.9mm_PTH  [TEST_HOLE]
TP2  1mm_SMD  [TEST_SMD]
TP3  D0.9mm_PTH  [TEST_HOLE]
U1  ETA6003Q3Q  [DFN16_0D5_ETA6003]
sheet PAGE07_T41_INTERFACE01
C36  1uF/10V  [C0402]
C45  1uF/10V  [C0402]
C144  1uF/6.3V  [C0402]
C145  100nF/6.3V  [C0402]
C146  1uF/6.3V  [C0402]
C147  100nF/6.3V  [C0402]
C174  1uF/6.3V  [C0402]
C175  100nF/6.3V  [C0402]
D4  ESD5451X  [ESD0402]
D5  ESD5451X  [ESD0402]
FB9  1000ohm/250mA  [FB0402]
FB10  1000ohm/250mA  [FB0402]
J4  CON4 1.0mm WT  [CON4-1D0-WT]
R38  33R  [R0402]
R39  33R  [R0402]
R40  10K  [R0402]
R42  10K  [R0402]
R45  10K  [R0402]
R46  10K  [R0402]
R47  100K  [R0402]
R48  33R  [R0402]
R49  470R  [R0402]
R50  100R  [R0402]
R51  33R  [R0402]
R53  10K  [R0402]
R143  0R  [R0402]
R175  33R  [R0402]
R176  0R  [R0402]
R177  0R  [R0402]
R178  0R  [R0402]
R179  33R  [R0402]
R180  33R  [R0402]
R181  0R  [R0402]
R182  0R  [R0402]
R183  0R  [R0402]
R184  0R  [R0402]
U9  CW2015CHBD  [QFN8_0D5_CW2015]
sheet PAGE08_T41_INTERFACE02
C148  100nF/6.3V  [C0402]
C170  1uF/6.3V  [C0402]
C171  100nF/6.3V  [C0402]
C172  1uF/6.3V  [C0402]
C173  100nF/6.3V  [C0402]
R123  100K  [R0402]
R138  0R  [R0402]
R185  0R  [R0402]
U7  T41 BGA232  [BGA232_0D65_T41]  (sections A,B,C,D)
U18  MX25L12833F  [WSOP8_1D27]
sheet PAGE10_SLCD_BT656
C103  1uF/6.3V  [C0402]
C104  100nF/6.3V  [C0402]
C105  1uF/6.3V  [C0402]
C106  100nF/6.3V  [C0402]
C109  10uF/10V-0603  [C0603]
C110  1uF/10V  [C0402]
C179  1uF/6.3V  [C0402]
C180  100nF/6.3V  [C0402]
C182  470nF/16V  [C0402]
C183  470nF/16V  [C0402]
C184  1uF/16V  [C0402]
C185  1uF/16V  [C0402]
J12  HEADER14 2.54mm MALE  [HEADER7X2M_2D54]
J15  CON37 0.5mm QCHX  [LCD_CON37_0D5_WTXG_MTF28]
R130  0R  [R0402]
R144  0R  [R0402]
R145  0R  [R0402]
R146  0R  [R0402]
R147  0R-0603  [R0603]
R148  0R-0603  [R0603]
R149  0R  [R0402]
R150  0R  [R0402]
R151  0R-0603  [R0603]
R154  0R  [R0402]
R155  0R  [R0402]
R156  0R  [R0402]
R157  0R  [R0402]
R158  0R  [R0402]
R160  0R  [R0402]
R161  0R  [R0402]
R162  0R  [R0402]
R163  0R  [R0402]
R164  0R  [R0402]
R166  0R  [R0402]
R168  0R  [R0402]
R169  0R  [R0402]
R170  0R  [R0402]
R171  0R  [R0402]
R172  0R  [R0402]
R174  0R  [R0402]
R212  10K  [R0402]
R214  7.68K/1%  [R0402]
U23  SGM3124  [TQFN16_0D5_SGM3124]
sheet PAGE12_WIFI_MOUDLE
C111  100nF/6.3V  [C0402]
C112  100nF/6.3V  [C0402]
C113  4.7uF/6.3V  [C0402]
C114  100nF/25V  [C0402]
J9  HEADER18 1.27mm Male  [HEADER9X2M_1D27]
J14  HEADER18 1.27mm Male  [HEADER9X2M_1D27]
R98  0R  [R0402]
R139  0R  [R0402]
R186  0R-0603  [R0603]
R187  0R  [R0402]
R188  0R  [R0402]
R213  0R  [R0402]
R215  0R  [R0402]
R218  0R  [R0402]
R220  0R  [R0402]
R223  0R  [R0402]
R225  0R  [R0402]
R229  0R  [R0402]
R230  0R  [R0402]
R246  100K  [R0402]
R247  100K  [R0402]
R248  100K  [R0402]
R249  100K  [R0402]
R250  100K  [R0402]
sheet PAGE13_ETH_PHY
C116  10uF/6.3V  [C0402_E]
C117  100nF/6.3V  [C0402]
C118  10uF/6.3V  [C0402_E]
C119  100nF/6.3V  [C0402]
C149  10uF/6.3V  [C0402_E]
C150  100nF/6.3V  [C0402]
C151  100nF/6.3V  [C0402]
C152  10uF/6.3V  [C0402_E]
C153  100nF/6.3V  [C0402]
C154  100nF/6.3V  [C0402]
C155  100nF/6.3V  [C0402]
C156  100nF/6.3V  [C0402]
C157  1nF/2KV-1206  [C1206]
D17  P3100SC  [SMB]
J13  RJ45 With Led  [RJ45-LED-1A]
R189  1.5K  [R0402]
R190  33R  [R0402]
R191  33R  [R0402]
R192  10K  [R0402]
R193  10K  [R0402]
R194  2.49K/1%  [R0402]
R195  33R  [R0402]
R196  10K  [R0402]
R197  10K  [R0402]
R198  33R  [R0402]
R199  10K  [R0402]
R200  10K  [R0402]
R201  10K  [R0402]
R202  10K  [R0402]
R203  10K  [R0402]
R204  0R  [R0402]
R205  10K  [R0402]
R206  10K  [R0402]
R207  10K  [R0402]
R209  10K  [R0402]
R210  0R  [R0402]
R211  300R  [R0402]
R217  300R  [R0402]
R221  75R/1%-0603  [R0603]
U19  SZ18201  [QFN32_0D5_SZ18201]
U20  FC1680C  [QFP16_1D27]
sheet PAGE14_PIR_LDR
C120  100nF/6.3V  [C0402]
C121  100nF/10V  [C0402]
C122  1uF/10V  [C0402]
C123  1uF/10V  [C0402]
C124  100nF/10V  [C0402]
C125  100nF/6.3V  [C0402]
C126  100nF/10V  [C0402]
C127  100nF/6.3V  [C0402]
C128  10uF/6.3V  [C0402_E]
C187  100nF/6.3V  [C0402]
C188  10uF/6.3V  [C0402_E]
C189  1uF/6.3V  [C0402]
C190  470nF/25V  [C0402]
C191  10nF/25V  [C0402]
C192  1nF/50V  [C0402]
C193  220pF/50V  [C0402]
C194  100nF/6.3V  [C0402]
C195  10nF/6.3V  [C0402]
C196  100nF/6.3V  [C0402]
C197  4.7uF/6.3V  [C0402]
C198  100nF/6.3V  [C0402]
C199  10nF/6.3V  [C0402]
C200  10nF/6.3V  [C0402]
C201  100nF/6.3V  [C0402]
C202  4.7uF/6.3V  [C0402]
C203  100nF/6.3V  [C0402]
C204  100nF/6.3V  [C0402]
D18  RB521CS-30  [SOD923_RB521CS-30]
Q4  XYC-PTJZ5E550BC-IC-C  [PD2_2D54]
Q5  WNM2016  [SOT23]
Q6  WPM3401  [SOT23]
Q7  WPM3401  [SOT23]
R92  10K/1%  [R0402]
R111  0R-0603  [R0603]
R112  100K  [R0402]
R113  0R  [R0402]
R114  100R  [R0402]
R115  100K/1%  [R0402]
R226  27K/1%  [R0402]
R227  15M/1%  [R0402]
R228  20K/1%  [R0402]
R252  499K/1%  [R0402]
R253  15M/1%  [R0402]
R254  10M/1%  [R0402]
R255  20K/1%  [R0402]
R256  100K/1%  [R0402]
R257  0R-0603  [R0603]
R258  15M/1%  [R0402]
R259  1M/1%  [R0402]
R260  10M/1%  [R0402]
R261  0R-0603  [R0603]
R262  15M/1%  [R0402]
R263  15M/1%  [R0402]
R264  100K/1%  [R0402]
R265  1M/1%  [R0402]
R266  15M/1%  [R0402]
R267  39K/1%  [R0402]
R268  39K/1%  [R0402]
R269  39K/1%  [R0402]
TP11  1mm_SMD  [TEST_SMD]
U15  S-1339D33  [SOT23-5]
U16  XYC-PIR203CJZ-S0  [DIP3_PIR]
U24  SGM8044  [TSSOP14_0D65_SGM8044]  (sections A,B,C,D)
U25  P904B-S  [DIP4_P904B_S]

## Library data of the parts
BT1 = BATTERY: 2.54mm Pitch 2P LC PTH Connector; Part Number: 04.0036.00; Part Type: 2.54mm立插电池座; 规格型号1: 2.54mm立插2P
C1 C8 C36 C45 C110 C122 C123 = CAP: Capacitor-1uF,+/-10%,X5R,10V-0402; Part Number: 02.0016.00; Part Type: 0402表贴普通电容; 供应商: Murata; 规格型号1: GRT155R61A105KE01D; 联系人: 谢苏云; 手机: 15900554174; 邮箱: susan.xie@murata.com
C2 C3 = CAP: Capacitor-22uF,+/-20%,X5R,10V-0603，不推荐（替代料不好寻）; Part Number: 02.0039.00; Part Type: 0603表贴普通电容; 供应商: Murata; 规格型号1: GRM188R61A226ME15D; 联系人: 谢苏云; 手机: 15900554174; 邮箱: susan.xie@murata.com
C4 C195 C199 C200 = CAP: Capacitor-10nF,+/-10%,X7R,6.3V-0402; Part Number: 02.0075.00; Part Type: 0402表贴普通电容; 供应商: Murata; 规格型号1: GRM155R70J102KA01D; 联系人: 谢苏云; 手机: 15900554174; 邮箱: susan.xie@murata.com
C5 C9 C121 C124 C126 = CAP: Capacitor-100nF,+/-10%,X7R,10V-0402; Part Number: 02.0075.00; Part Type: 0402表贴普通电容; 供应商: Murata; 规格型号1: GRM155R71A104KA01D; 联系人: 谢苏云; 手机: 15900554174; 邮箱: susan.xie@murata.com
C6 C7 C109 = CAP: Capacitor-10uF,+/-20%,X5R,10V-0603; Part Number: 02.0026.00; Part Type: 0603表贴普通电容; 供应商: YAGEO / Murata; 规格型号1: CC0603MRX5R6BB106 / GRM188R61A106KE47D; 联系人: 谢苏云; 手机: 15900554174; 邮箱: susan.xie@murata.com
D1 D2 = ESD: Murata Vbr=7V Cj=0.5pF Bidirection ESD Protection Device; Part Number: 09.0042.00; 供应商: Murata; 联系人: 谢苏云; 手机: 15900554174; 邮箱: susan.xie@murata.com; Datasheet: ESD-LXES1UTAA1-157.pdf
D3-D5 = ESD: WILL ESD5451X-2/TR Bidirection 17.5pF Transient Voltage Suppressor; Part Number: 09.0006.00; 供应商: Will; 规格型号1: ESD5451X-2/TR; 联系人: 安志鹏; 手机: 18321800431; 邮箱: an.zhipeng@sh-willsemi.com; Datasheet: ESD5451X.pdf
J1 = SW3: POWER SWITCH 3Pin 4.45mm Pitch; Part Number: 04.2001.00; Part Type: 拨动开关; 规格型号1: SS12D10
J2 = MICROUSB_0: USB Connector  MICRO USB 带牛角有卷边无柱; Part Number: 04.0023.00; Part Type: USB连接器; 供应商: 深圳旺科达; 规格型号1: MicroB USB母座; 联系人: 童国相; 手机: 13824380089; 邮箱: wangkeda2008@163.com; Datasheet: MICRO USB 带牛角有卷边无柱.pdf
L1 = INDUCTOR: MuRata DFE252012P-2R2MS=P2 2.2uH/2.2A-2520 POWER INDUCTOR; Part Number: 03.0021.00; Part Type: 2520表贴电感; 供应商: Murata; 规格型号1: DFE252012P-2R2MS=P2; 联系人: 谢苏云; 手机: 15900554174; 邮箱: susan.xie@murata.com; Datasheet: DFE252012P_Murata data sheet150828.pdf
R1 = RES: Resistor-300R,+/-5%,1/10W-0603; Part Number: 01.0053.00; Part Type: 0603表贴普通电阻; 供应商: 厚声; 规格型号1: 0603WAJ0301T5E
R2 = RES: Resistor-750K,+/-1%,1/16W-0402; Part Number: 01.0096.00; Part Type: 0402表贴高精度电阻; 供应商: 厚声; 规格型号1: 0402WGF7503TCE
R3 R252 = RES: Resistor-499K,+/-1%,1/16W-0402; Part Number: 01.0116.00; Part Type: 0402表贴高精度电阻; 供应商: 厚声; 规格型号1: 0402WGF4993TCE
R4 R5 R9 R40 R42 R45 R46 R192 R193 R196 R197 R199-R203 R205-R207 R209 R212 = RES: Resistor-10K,+/-5%,1/16W-0402; Part Number: 01.0023.00; Part Type: 0402表贴普通电阻; 供应商: 厚声; 规格型号1: 0402WGJ0103TCE
R6 = RES: Resistor-560R,+/-1%,1/16W-0402; Part Number: 01.0092.00; Part Type: 0402表贴高精度电阻; 供应商: 厚声; 规格型号1: 0402WGF5600TCE
R7 = RES: Resistor-2K,+/-1%,1/16W-0402; Part Number: 01.0016.00; Part Type: 0402表贴高精度电阻; 供应商: 厚声; 规格型号1: 0402WGF2001TCE
R8 R10 R11 R47 R112 R123 R246-R250 = RES: Resistor-100K,+/-5%,1/16W-0402; Part Number: 01.0041.00; Part Type: 0402表贴普通电阻; 供应商: 厚声; 规格型号1: 0402WGJ0104TCE
R12 = RES: Resistor-200K,+/-1%,1/16W-0402; Part Number: 01.0045.00; Part Type: 0402表贴高精度电阻; 供应商: 厚声; 规格型号1: 0402WGF2003TCE
TP1 TP3 = TP: PTH Test Point φ1.78mm Drill 0.89mm; Part Number: AA.0002.00; Part Type: Test Point
TP2 TP11 = TP: SMD Test Point φ1mm; Part Number: AA.0001.00; Part Type: Test Point
U1 = ETA6003: ETA ETA6003 2.5A, 3MHz Switching Charger with Dynamic Power Path Management; Part Number: 06.0106.00; Part Type: 充电芯片; 供应商: ETA; 联系人: 徐卓荣; 手机: 13923780263; 邮箱: xuzhuorong@etasolution.com; Datasheet: ETA6003 v2.5.1.pdf
C103 C105 C144 C146 C170 C172 C174 C179 C189 = CAP: Capacitor-1uF,+/-10%,X7R,6.3V-0402; Part Number: 02.0076.00; Part Type: 0402表贴普通电容; 供应商: Murata; 规格型号1: GRM155R70J105KA12; 联系人: 谢苏云; 手机: 15900554174; 邮箱: susan.xie@murata.com
C104 C106 C111 C112 C117 C119 C120 C125 C127 C145 C147 C150 C151 C153-C156 C171 C173 C175 C180 C187 C194 C198 C201 C203 C204 = CAP: Capacitor-100nF,+/-10%,X7R,6.3V-0402; Part Number: 02.0075.00; Part Type: 0402表贴普通电容; 供应商: Murata; 规格型号1: GRM155R70J104KA01D; 联系人: 谢苏云; 手机: 15900554174; 邮箱: susan.xie@murata.com
FB9 FB10 = BEAD: Murata BLM15HG102SN1D Z=1000ohm@100MHz 250mA 1.1ohm 25%; Part Number: 03.1001.00; Part Type: 0402表贴磁珠; 供应商: Murata; 规格型号1: BLM15HG102SN1D; 联系人: 谢苏云; 手机: 15900554174; 邮箱: susan.xie@murata.com; Datasheet: BLM15HG.pdf
J4 = CON_4X1: HOLY 1.0mm Pitch 4P WT SMD Connector; Part Number: 04.0004.00; Part Type: 1.0mm卧贴连接器; 供应商: 深圳宏利电子; 规格型号1: 1mm卧贴4P插座; 联系人: 谢素平; 手机: 16717558767; Datasheet: 1.0mmA 卧贴.pdf
R38 R39 R48 R51 R175 R179 R180 R190 R191 R195 R198 = RES: Resistor-33R,+/-5%,1/16W-0402; Part Number: 01.0005.00; Part Type: 0402表贴普通电阻; 供应商: 厚声; 规格型号1: 0402WGJ0330TCE
R49 = RES: Resistor-470R,+/-5%,1/16W-0402; Part Number: 01.0114.00; Part Type: 0402表贴普通电阻; 供应商: 厚声; 规格型号1: 0402WGJ0471TCE
R50 R114 = RES: Resistor-100R,+/-5%,1/16W-0402; Part Number: 01.0078.00; Part Type: 0402表贴普通电阻; 供应商: 厚声; 规格型号1: 0402WGJ0101TCE
R53 = RES: Resistor-10K,+/-5%,1/16W-0402; Part Number: 01.0023.00; Part Type: 0402表贴普通电阻; 供应商: 厚声; 供应商1: Eyang; 规格型号1: 0402WGJ0103TCE; 联系人1: 何俊; 手机1: 18317187178; 邮箱1: hejunxs@szeyang.com
R98 R113 R130 R138 R139 R143-R146 R149 R150 R154-R158 R160-R164 R166 R168-R172 R174 R176-R178 R181-R185 R187 R188 R204 R210 R213 R215 R218 R220 R223 R225 R229 R230 = RES: Resistor-0R,+/-5%,1/16W-0402; Part Number: 01.0001.00; Part Type: 0402表贴普通电阻; 供应商: 厚声; 规格型号1: 0402WGJ0000TCE
U9 = CW2015: Cellwise CW2015 Low-Cost Fuel Gauge IC with Low-SOC Alert; Part Number: 06.0090.00; Part Type: 库仑计; 供应商: Cellwise; 联系人: 肖华; 手机: 18929353767; 邮箱: andy.xiao@cellwise-semi.com; Datasheet: CW2015CHBD-DS V1.3_EN.pdf
C148 = CAP: Capacitor-100nF,+/-10%,X7R,6.3V-0402; ID: 15; Part Number: 02.0075.00; Part Type: 0402表贴普通电容; 供应商: Murata; 供应商1: Eyang; 规格型号1: GRM155R70J104KA01D; 联系人: 谢苏云; 联系人1: 何俊; 手机: 15900554174; 手机1: 18317187178; 邮箱: susan.xie@murata.com; 邮箱1: hejunxs@szeyang.com
U7 = T41_BGA232: Ingenic T41 Smart Video Processor FBGA 232Ball 0.65mmPitch 11mmX11mm; Part Number: 06.0137.00; Part Type: CPU; 供应商: Ingenic; 规格型号1: T41
U18 = SPI_NOR: MACRONIX MX25L12833F 3V 128Mbit CMOS MXSMIO SPI NOR FLASH MEMORY; Part Number: 06.0015.02; Part Type: SPI NOR; 供应商: 旺宏; 联系人: 李永坚; 手机: 13646217175; 邮箱: jamesli01@mxic.com.cn; Datasheet: MX25L12833F, 3V, 128Mb, v1.0.pdf
C182 C183 = CAP: Capacitor-470nF,+/-10%,X5R,16V-0402; Part Number: 02.0041.00; Part Type: 0402表贴普通电容; 供应商: YAGEO / Murata; 规格型号1: CC0402KRX5R7BB474 / GRM155R61C474KE01D; 联系人: 谢苏云; 手机: 15900554174; 邮箱: susan.xie@murata.com
C184 C185 = CAP: Capacitor-1uF,+/-10%,X5R,16V-0402; Part Number: 02.0016.00; Part Type: 0402表贴普通电容; 供应商: YAGEO / Murata; 规格型号1: CC0402KRX5R7BB105 / GRM155R61C105KA12D; 联系人: 谢苏云; 手机: 15900554174; 邮箱: susan.xie@murata.com
J12 = HEADER_7x2: HEADER 7X2 2.54mm MALE; Part Number: 04.0037.00; Part Type: 2.54mm双排插针; 规格型号1: 2.54mm 2X7双排排针
J15 = MTF0280QT-30: 迈高达 MTF0280QT-30 2.8寸 SLCD FPC连接器; Part Number: 04.0137.00; Part Type: 2.8寸LCD屏FPC连接器; 供应商: 迈高达; Datasheet: MTF0280QT-30-SPEC(1123).pdf
R111 R147 R148 R151 R186 R257 R261 = RES: Resistor-0R,+/-5%,1/10W-0603; Part Number: 01.0051.00; Part Type: 0603表贴普通电阻; 供应商: 厚声; 规格型号1: 0603WAJ0000T5E
R214 = RES: Resistor-7.68K,+/-1%,1/16W-0402; Part Number: 01.0094.00; Part Type: 0402表贴高精度电阻; 供应商: 厚声; 规格型号1: 0402WGF7681TCE
U23 = SGM3124: SGMICRO SGM3124 White LED Charge Pump Current Source with PWM Brightness Control; Part Number: 06.0064.00; Part Type: 驱动芯片; 供应商: SGMICRO; 规格型号1: SGM3124YTQ16G/TR; 联系人: 王哲; 手机: 18406666893; 邮箱: jayden_wang@sg-micro.com; Datasheet: SGM3124 REV.A.1_20130111.pdf
C113 C197 C202 = CAP: Capacitor-4.7uF,+/-20%,X5R,6.3V-0402; Part Number: 02.0018.00; Part Type: 0402表贴普通电容; 供应商: YAGEO / Murata; 规格型号1: CC0402MRX5R5BB475 / GRM153R60J475ME15D; 联系人: 谢苏云; 手机: 15900554174; 邮箱: susan.xie@murata.com
C114 = CAP: Capacitor-100nF,+/-10%,X5R,25V-0402; Part Number: 02.0038.00; Part Type: 0402表贴普通电容; 供应商: YAGEO / Murata; 规格型号1: CC0402KRX5R8BB104 / GRM155R71E104KE14D; 联系人: 谢苏云; 手机: 15900554174; 邮箱: susan.xie@murata.com
J9 J14 = HEADER_9X2: HEADER 9X2 1.27mm MALE; Part Number: 04.0066.00; Part Type: 1.27mm双排插针; 规格型号1: 1.27mm 2X9双排排针
C116 C118 C149 C152 = CAP: Capacitor-10uF,+/-20%,X5R,6.3V-0402+; Part Number: 02.0034.00; Part Type: 0402表贴普通电容; 供应商: YAGEO / Murata; 供应商2: Murata; 规格型号1: CC0402MRX5R5BB106 / GRM155R60J106ME44D; 联系人: 谢苏云; 联系人2: 吴铭; 手机: 15900554174; 手机2: 13761466262; 邮箱: susan.xie@murata.com; 邮箱2: cherry.wu@murata.com
C157 = CAP: Capacitor-1nF,+/-10%,X7R,2KV-1206; Part Number: 02.0030.00; Part Type: 1206表贴高压电容; 供应商: YAGEO / Murata; 规格型号1: CC1206KKX7RDBB102 / GR431BR7LA102KW66L; 联系人: 谢苏云; 手机: 15900554174; 邮箱: susan.xie@murata.com
D17 = P3100: BrightKing P3100SC 防雷管 半导体放电管 10/700us_6000V; Part Number: 09.0010.00; Part Type: 防护二极管; Datasheet: P3100.pdf
J13 = RJ45_1x1_LED: RJ45-LED-1A Ethernet Connector With LED; Part Number: 10.0001.00; Part Type: 网口连接座; 规格型号1: RJ45带灯; Datasheet: PCB-937带灯.pdf
R189 = RES: Resistor-1.5K,+/-5%,1/16W-0402; Part Number: 01.0085.00; Part Type: 0402表贴普通电阻; 供应商: 厚声; 规格型号1: 0402WGJ0152TCE
R194 = RES: Resistor-2.49K,+/-1%,1/16W-0402; Part Number: 01.0134.00; Part Type: 0402表贴高精度电阻; 供应商: 厚声; 规格型号1: 0402WGF2491TCE
R211 R217 = RES: Resistor-300R,+/-5%,1/16W-0402; Part Number: 01.0011.00; Part Type: 0402表贴普通电阻; 供应商: 厚声; 规格型号1: 0402WGJ0301TCE
R221 = RES: Resistor-75R,+/-1%,1/10W-0603; Part Number: 01.0052.00; Part Type: 0603表贴高精度电阻; 供应商: 厚声; 规格型号1: 0603WAF750JT5E
U19 = SZ18201: Motor Comm SZ18201 Single Chip 10/100M Ethernet Phyceiver with Auto MDIX; Part Number: 06.0123.00; Part Type: ETH Phy 芯片; 供应商: Motor Comm; Datasheet: SZ18201_2021-05-28.PDF
U20 = FC1680C: IC-FLY FC1680C 10/100 Small Package Transformer module; Part Number: 06.0010.00; Part Type: 网络变压器; 供应商: 上海飞芯电子; 联系人: 刘经纬; 手机: 18621560356; Datasheet: FC1680C.20120213.pdf
C128 C188 = CAP: Capacitor-10uF,+/-20%,X5R,6.3V-0402+; Part Number: 02.0034.00; Part Type: 0402表贴普通电容; 供应商: YAGEO / Murata; 规格型号1: CC0402MRX5R5BB106 / GRM155R60J106ME44D; 联系人: 谢苏云; 手机: 15900554174; 邮箱: susan.xie@murata.com
C190 = CAP: Capacitor-470nF,+/-10%,X5R,25V-0402; Part Number: 02.0041.00; Part Type: 0402表贴普通电容; 供应商: Murata; 规格型号1: GRM155R61E474KE01D; 联系人: 谢苏云; 手机: 15900554174; 邮箱: susan.xie@murata.com
C191 = CAP: Capacitor-10nF,+/-10%,X7R,25V-0402; Part Number: 02.0012.00; Part Type: 0402表贴普通电容; 供应商: YAGEO / Murata; 规格型号1: CC0402KRX7R8BB103 / GCM155R71E103KA37D; 联系人: 谢苏云; 手机: 15900554174; 邮箱: susan.xie@murata.com
C192 = CAP: Capacitor-1nF,+/-10%,X7R,50V-0402; Part Number: 02.0011.00; Part Type: 0402表贴普通电容; 供应商: YAGEO / Murata; 规格型号1: CC0402KRX7R9BB102 / GCM155R71H102KA37D; 联系人: 谢苏云; 手机: 15900554174; 邮箱: susan.xie@murata.com
C193 = CAP: Capacitor-220pF,+/-10%,X7R,50V-0402; Part Number: 02.0048.00; Part Type: 0402表贴普通电容; 供应商: YAGEO / Murata; 规格型号1: CC0402KRX7R9BB221 / GRM155R71H221KA01D; 联系人: 谢苏云; 手机: 15900554174; 邮箱: susan.xie@murata.com
C196 = CAP: Capacitor-100nF,+/-10%,X7R,6.3V-0402; Part Number: 02.0075.00; Part Type: 0402表贴普通电容; 供应商: Murata; 供应商1: Eyang; 规格型号1: GRM155R70J104KA01D; 联系人: 谢苏云; 联系人1: 何俊; 手机: 15900554174; 手机1: 18317187178; 邮箱: susan.xie@murata.com; 邮箱1: hejunxs@szeyang.com
D18 = DIODE: ROHM RB521CS-30 Schottky Barrier Diode Vr 30V; Part Number: 09.0027.00; Part Type: 二极管; 供应商: ROHM; 联系人: 贾文; 手机: 13817895109; 邮箱: jossie-jia@rohm.com.cn; Datasheet: RB521CS-30.pdf
Q4 = PHOTO_DIODE: 鑫永诚 PHOTO_DIODE XYC-PTJZ5E550BC-IC-C series VCC=5V; Part Number: 07.1011.00; Part Type: 光敏三极管; 供应商: 鑫永诚; 规格型号1: PT5E550BC; 联系人: 陈名雄; 手机: 18924589333; 邮箱: sales03@xycgd.com; Datasheet: XYC-PTJZ5E550BC-IC-C.pdf
Q5 = N_MOS: WILL WNM2016 N-Channel MOSFET; Part Number: 09.0009.00; Part Type: MOS管; 供应商: Will; 联系人: 安志鹏; 手机: 18321800431; 邮箱: an.zhipeng@sh-willsemi.com
Q6 Q7 = P_MOS: WILL WPM3401 P-Channel MOSFET; Part Number: 09.0008.00; Part Type: MOS管; 供应商: Will; 联系人: 安志鹏; 手机: 18321800431; 邮箱: an.zhipeng@sh-willsemi.com; Datasheet: WPM340_datasheet.pdf
R92 = RES: Resistor-10K,+/-1%,1/16W-0402; Part Number: 01.0024.00; Part Type: 0402表贴高精度电阻; 供应商: 厚声; 规格型号1: 0402WGF1002TCE
R115 R256 R264 = RES: Resistor-100K,+/-1%,1/16W-0402; Part Number: 01.0040.00; Part Type: 0402表贴高精度电阻; 供应商: 厚声; 规格型号1: 0402WGF1003TCE
R226 = RES: Resistor-27K,+/-1%,1/16W-0402; Part Number: 01.0029.00; Part Type: 0402表贴高精度电阻; 供应商: 厚声; 规格型号1: 0402WGF2702TCE
R227 R253 R258 R262 R263 R266 = RES: Resistor-15M,+/-1%,1/16W-0402; Part Number: 01.0123.00; Part Type: 0402表贴高精度电阻; 供应商: 厚声; 规格型号1: 0402WGF1505TCE
R228 R255 = RES: Resistor-20K,+/-1%,1/16W-0402; Part Number: 01.0113.00; Part Type: 0402表贴高精度电阻; 供应商: 厚声; 规格型号1: 0402WGF2002TCE
R254 R260 = RES: Resistor-10M,+/-1%,1/16W-0402; Part Number: 01.0122.00; Part Type: 0402表贴高精度电阻; 供应商: 厚声; 规格型号1: 0402WGF1005TCE
R259 R265 = RES: Resistor-1M,+/-1%,1/16W-0402; Part Number: 01.0048.00; Part Type: 0402表贴高精度电阻; 供应商: 厚声; 规格型号1: 0402WGF1004TCE
R267-R269 = RES: Resistor-39K,+/-1%,1/16W-0402; Part Number: 01.0033.00; Part Type: 0402表贴高精度电阻; 供应商: 厚声; 规格型号1: 0402WGF3902TCE
U15 = SGM2019: SII S-1339D33 300mA Input-1.5V~5.5V LDO Regulator; Part Number: 05.0028.00; Part Type: LDO; 供应商: SII; 规格型号1: S-1339D33-M5T1U3; 联系人: 张艳虹; 手机: 13611945636; 邮箱: alex.zhang@sii.co.jp; Datasheet: S1339_C5.8_00.pdf
U16 = PIR: 鑫永诚  XYC-PIR203CJZ-S0 Danalog Pyroelectric passive infrared sensor; Part Number: 07.1012.00; 供应商: 鑫永诚; 联系人: 陈名雄; 手机: 18924589333; 邮箱: sales03@xycgd.com; Datasheet: XYC-PIR203CJZ-S0.pdf
U24 = OPAMP_4: SGM SGM8044 Quad Rail-to-Rail I/O Operational Amplifier; Part Number: 06.0102.00; Part Type: 运放IC; 供应商: SGMICRO; 联系人: 王哲; 手机: 18406666893; 邮箱: jayden_wang@sg-micro.com; Datasheet: SGM8044?REV.A.4_20171012.pdf
U25 = PIR_4: Nicera P904B-S Digital Pyroelectric passive infrared sensor; Part Number: 07.1009.00; Part Type: PIR; 供应商: Nicera; 联系人: 杨生; 手机: 13002160560; Datasheet: PIR目录.pdf

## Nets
1V8: R139.2 ; also on sheet 10 12
3V3: C116.1 C117.1 C120.1 C148.2 Q4.1(BASE) R98.2 R112.2 R123.2 R147.1 R148.1 R151.1 R157.2 R189.1 R192.1 R196.1 R199.1 R202.1 R205.1 R207.1 R210.2 U18.8(VCC) U19.14(DVDD33_1) ; also on sheet 10 12 13 14 15
AVDD33: C152.1 C153.1 R209.2 R210.1 U19.7(AVDD33_1)
GND: BT1.2(-) C1.2 C2.2 C3.2 C4.2 C5.2 C6.2 C7.2 C8.2 C9.2 C36.2 C45.2 C103.2 C104.2 C105.2 C106.2 C109.2 C110.2 C111.2 C112.2 C113.2 C114.2 C116.2 C117.2 C118.2 C119.2 C120.2 C121.2 C122.2 C123.2 C124.2 C125.2 C126.2 C127.2 C128.2 C144.2 C145.2 C146.2 C147.2 C148.1 C149.2 C150.2 C151.2 C152.2 C153.2 C154.1 C155.1 C156.1 C157.1 C170.2 C171.2 C172.2 C173.2 C174.2 C175.2 C179.2 C180.2 C184.1 C185.1 C187.2 C188.2 C189.2 C190.2 C191.2 C192.2 C193.2 C194.2 C196.2 C198.2 C201.2 C202.2 C203.2 C204.2 D1.1(ANODE) D2.1(ANODE) D3.1(ANODE) D4.1(ANODE) D5.1(ANODE) D17.2 J2.5(GND1) J2.6(GND2) J2.7(GND3) J2.8(GND4) J2.9(GND5) J2.10(GND6) J2.11(GND7) J4.2 J4.5(S1) J4.6(S2) J9.3 J9.4 J9.8 J9.9 J9.12 J9.13 J9.15 J9.16 J12.4 J12.13 J12.14 J13.9(SH1) J13.10(SH2) J13.12(CON_PIN[11]) J13.14(CON_PIN[13]) J14.9 J14.10 J14.15 J14.18 J15.1(DB1) J15.2(DB2) J15.3(DB3) J15.4(DB4) J15.5(GND1) J15.22(DB5) J15.34(GND2) J15.35(DB6) J15.36(DB7) J15.37(DB8) J15.38(G1) J15.39(G2) R1.1 R3.1 R5.2 R6.1 R7.1 R11.1 R12.1 R53.2 R115.1 R193.2 R194.2 R197.2 R200.2 R201.1 R203.2 R204.1 R206.2 R212.2 R214.2 R226.1 R259.1 R262.1 R266.1 R267.1 R268.1 R269.1 U1.5(PGND) U1.6(ENB) U1.8(ENPPB) U1.10(GND) U1.17(EPAD) U7.N5(CSI_VSSA) U9.1(CTG) U9.4(GND) U15.2(GND) U16.3(GND) U18.4(GND) U19.33(GND) U23.7(PGND) U23.14(GND) U23.17(POWER_PAD) U24.11 U25.1(VSS) ; also on sheet 10 11 12 13 14 15
VBAT2: BT1.1(+) C8.1 R2.2 R49.2 R50.2 U1.14(BATT_0) U1.16(BATT_1)
VCC_5V: C2.1 C6.1 C7.1 C184.2 D3.2(CATHODE) J2.1(VBUS) R4.2 R9.2 R10.2 TP1.1 U1.2(IN) U23.13(VIN) ; also on sheet 12
VCC_IN: C3.1 C4.1 J1.1 L1.2 U1.1(SYS_0) U1.15(SYS_1)
VCC_SOC: C109.1 C110.1 J12.1 J12.2 ; also on sheet 10 13 15
VCC_SYS: C1.1 J1.2 R111.1 TP2.1 ; also on sheet 10
VDD_TFT: C103.1 C104.1 J15.6(VDD1) R151.2
VDDIO2: C172.1 C173.1 R138.2 R185.2 U7.C4(VDDIO2)
ALS_Measure_EN_PB22: R112.1 R114.2 U7.D15(MSC1_D3_PB22)
BAT_ADC_IoT: C5.1 J14.14 R2.1 R3.2
BAT_ALRT_N_IoT: J14.3 R47.2 U9.5(~{ALRT})
BT656_D0_PD00: J12.5 R144.2
BT656_D1_PD01: J12.6 R146.2
BT656_D2_PD02: J12.7 R150.2
BT656_D3_PD03: J12.8 R155.2
BT656_D4_PD04: J12.9 R158.2
BT656_D5_PD05: J12.10 R161.2
BT656_D6_PD06: J12.11 R163.2
BT656_D7_PD07: J12.12 R166.2
BT656_PCLK_PD08: J12.3 R169.2
BT_UART0_CTS_PC11: R218.1 U7.C5(I2S_DAC_MCLK_PC11)
BT_UART0_RTS_PC12: R223.1 U7.A5(I2S_ADC_MCLK_PC12)
BT_UART0_RXD_PC09: R213.1 U7.C6(SMB2_SCK_PC09)
BT_UART0_TXD_PC08: R187.1 U7.B6(SMB2_SDA_PC08)
BT_UART_CTS/PIR_PWR_EN_IoT: J14.7 R218.2 R220.2
BT_UART_RTS/LED_R_IoT: J14.6 R223.2 R225.2
BT_UART_RXD/USART2_TX_IoT: J14.8 R213.2 R215.2
BT_UART_TXD/USB_DET_IoT: J14.5 R187.2 R188.2
CHARG_DET_N_IoT: J14.4 R8.1 U1.9(STATS)
CLK_CTRL: R199.2 R200.1 U19.12(RXD[3]/CLK_CTL)
CSI_CLKN_DVP_D4: U7.M2(CSI_CLKN_DVP_D4) ; also on sheet 15
CSI_CLKP_DVP_D5: U7.L3(CSI_CLKP_DVP_D5) ; also on sheet 15
CSI_DATAN0_DVP_D0: U7.L2(CSI_DATAN0_DVP_D0) ; also on sheet 15
CSI_DATAN1_DVP_D2: U7.N1(CSI_DATAN1_DVP_D2) ; also on sheet 15
CSI_DATAP0_DVP_D1: U7.L1(CSI_DATAP0_DVP_D1) ; also on sheet 15
CSI_DATAP1_DVP_D3: U7.M3(CSI_DATAP1_DVP_D3) ; also on sheet 15
CSI_VCC08: C146.1 C147.1 FB9.1 U7.N2(CSI_VCCA08)
CSI_VCC18: C144.1 C145.1 FB10.1 U7.K3(CSI_VCCA18)
DVP_D6: U7.H2(SD0_DVP_D6_PA06) ; also on sheet 15
DVP_D7: U7.H3(SD1_DVP_D7_PA07) ; also on sheet 15
DVP_D8: U7.G1(SD2_DVP_D8_PA08) ; also on sheet 15
DVP_D9: U7.G2(SD3_DVP_D9_PA09) ; also on sheet 15
DVP_HSYNC: U7.J2(CS2_DVP_HSYNC_PA16) ; also on sheet 15
DVP_PCLK: U7.F3(SA0_DVP_PCLK__PA14) ; also on sheet 15
DVP_VSYNC: U7.J3(RD_DVP_VSYNC_PA17) ; also on sheet 15
EMMC_RST_PB21: U7.C17(MSC1_D2_TMS_PB21) ; also on sheet 13
GMAC_MDC: R177.2 U19.22(MDC)
GMAC_MDIO: R178.2 R189.2 U19.23(MDIO)
GMAC_NRST_PB28: C151.1 R207.2 U7.A11(DMIC_CLK_SMB2_SCK_PB28) U19.21(RESET_N)
GMAC_PHY_CLK: R175.2 U19.31(XTAL_IN)
GMAC_RXD0: R195.1 U7.U13(GMAC_RXD0_PWM6_PB15)
GMAC_RXD1: R192.2 R193.1 R198.1 U7.R12(GMAC_RXD1_PWM7_PB16)
GMAC_RXDV: R191.1 U7.U9(GMAC_RXDV_PWM3_PB09)
GMAC_TXCLK: R190.1 U7.T12(GMAC_TXCLK_PB06)
GMAC_TXD0: R179.2 U19.16(TXD[0])
GMAC_TXD1: R180.2 U19.17(TXD[1])
GMAC_TXEN: R176.2 U19.20(TXEN)
I2C0_MIPI_DVP_SCK: U7.J4(SD7_SMB0_SCK_PA13) ; also on sheet 15
I2C0_MIPI_DVP_SDA: U7.J1(SD6_SMB0_SDA_PA12) ; also on sheet 15
I2C1_SCK_PB26: R46.2 R184.1 U9.7(SCL) ; also on sheet 14
I2C1_SDA_PB25: R40.2 R182.1 U9.8(SDA) ; also on sheet 14
IRLED_EN_N_PB19: U7.D16(MSC1_CMD_PB19) ; also on sheet 15
KEY1_PB30: U7.C12(DMIC_DAT1_UART4_RXD_PB30) ; also on sheet 14
KEY_IoT_N: J9.18 ; also on sheet 14
LDR0: C125.1 R92.1 R113.1 ; also on sheet 12
LED_G: R181.1 ; also on sheet 14
LED_R_IoT: R225.1 ; also on sheet 14
MCU_PWR: R8.2 R47.1 R186.2 ; also on sheet 10 14
MIPI_DVP_IRCUTN_PB18: U7.E17(MSC1_D1_PB18) ; also on sheet 15
MIPI_DVP_IRCUTP_PB17: U7.E16(MSC1_D0_PB17) ; also on sheet 15
MIPI_DVP_MCLK: R38.1 ; also on sheet 15
MIPI_DVP_PWDN_PA19: R143.1 ; also on sheet 15
MIPI_DVP_RESET: U7.E3(SA2_PA18) ; also on sheet 15
MSC0_CLK: R39.2 ; also on sheet 13
MSC0_CMD: U7.G17(MSC0_CMD_PB05) ; also on sheet 13
MSC0_D0: U7.H16(MSC0_D0_PB00) ; also on sheet 13
MSC0_D1: U7.J15(MSC0_D1_PB01) ; also on sheet 13
MSC0_D2: U7.G15(MSC0_D2_PB02) ; also on sheet 13
MSC0_D3: U7.G16(MSC0_D3_PB03) ; also on sheet 13
NTC: R9.1 R11.2 TP3.1 U1.7(NTC)
OU_PWR_EN_PC18: U7.B5(SSI_SLV_DR_I2S_SDTI_PC18) ; also on sheet 10
PHY_LED0: R202.2 R203.1 R211.2 U19.24(LED0/PHYAD[0])
PHY_LED1: R205.2 R206.1 R217.2 U19.25(LED1/PHYAD[1])
PIR_3V3: C123.1 C124.1 C127.1 C196.1 D18.1(ANODE) R227.2 R228.1 R258.2 R265.2 TP11.1 U15.5(VOUT) U24.4 U25.3(VDD)
PIR_H_IoT: J14.11 Q6.1(GATE) U24.1
PIR_IoT: R230.1 R257.2 U25.4(REL)
PIR_L_IoT: J14.13 Q7.1(GATE) U24.7
PIR_PWR_EN_IoT: C126.1 D18.2(CATHODE) R220.1 U15.3(EN)
PWR_ON_PC16: J14.2 U7.A3(SSI_SLV_CE0_I2S_DAC_LRCK_PC16)
RMII_MDCK: R177.1 U7.R10(GMAC_MDCK_SMB2_SDA_PB10)
RMII_MDIO: R178.1 U7.T10(GMAC_MDIO_SMB2_SCK_PB11)
RMII_PHY_CLK: R175.1 U7.T9(GMAC_PHY_CLK_PB07)
RMII_TX0: R179.1 U7.R11(GMAC_TXD0_PWM4_PB13)
RMII_TX1: R180.1 U7.T11(GMAC_TXD1_PWM5_PB14)
RMII_TXEN: R176.1 U7.U11(GMAC_TXEN_PWM2_PB08)
RTC_IRQ_N_PB29: U7.B12(DMIC_DAT0_UART4_TXD_PB29) ; also on sheet 14
RX+: J13.3(CON_PIN[2]) U20.14(TX-/RX-)
RX-: J13.6(CON_PIN[5]) U20.16(TX+/RX+)
RX_N1: U19.6(TRXN1) U20.1(TD+/RD+)
RX_P1: U19.5(TRXP1) U20.3(TD-/RD-)
RXDV: R196.2 R197.1 U19.8(RXDV)
SD0_CD_N_PB27: U7.B11(DRV_VBUS_SMB2_SDA_PB27) ; also on sheet 13
SD_PWR_EN_N_PB20: U7.E15(MSC1_CLK_TCK_PB20) ; also on sheet 13
SENS1: C204.1 Q6.2(SOURCE) Q7.2(SOURCE) R265.1 R267.2 U25.2(SENS)
SFC1_CS_N: R123.1 U7.R7(SFC1_CE_PA29) U18.1(~{CS})
SFC1_SCLK: U7.T8(SFC1_CLK_PA22) U18.6(SCLK)
SFC1_SIO0: U7.R8(SFC1_DT_IO0_PA20) U18.5(SI/SIO0)
SFC1_SIO1: U7.T7(SFC1_DR_IO1_PA21) U18.2(SO/SIO1)
SFC1_SIO2: U7.U7(SFC1_WP_IO2_PA30) U18.3(~{WP}/SIO2)
SFC1_SIO3: U7.R9(SFC1_HOLD_IO3_PA31) U18.7(~{RESET}/SIO3)
SLCD_BLEN: R183.1 R212.1 U23.15(EN1) U23.16(EN2)
SLCD_BT656_D0: R130.1 R144.1 U7.A15(SLCD_D0_UART3_TXD_PD00)
SLCD_BT656_D1: R145.1 R146.1 U7.B15(SLCD_D1_UART3_RXD_PD01)
SLCD_BT656_D2: R149.1 R150.1 U7.A16(SLCD_D2_UART4_TXD_PD02)
SLCD_BT656_D3: R154.1 R155.1 U7.C15(SLCD_D3_UART4_RXD_PD03)
SLCD_BT656_D4: R156.1 R158.1 U7.A17(SLCD_D4_UART5_TXD_PD04)
SLCD_BT656_D5: R160.1 R161.1 U7.B16(SLCD_D5_UART5_RXD_PD05)
SLCD_BT656_D6: R162.1 R163.1 U7.B17(SLCD_D6_SMB1_SDA_PD06)
SLCD_BT656_D7: R164.1 R166.1 U7.C16(SLCD_D7_SMB1_SCK_PD07)
SLCD_CS: R171.1 U7.B13(SLCD_CS_PWM5_PD10)
SLCD_CS_PD10: J15.7(CS) R171.2
SLCD_D0_PD00: J15.23(DB10) R130.2
SLCD_D1_PD01: J15.24(DB11) R145.2
SLCD_D2_PD02: J15.25(DB12) R149.2
SLCD_D3_PD03: J15.26(DB13) R154.2
SLCD_D4_PD04: J15.27(DB14) R156.2
SLCD_D5_PD05: J15.28(DB15) R160.2
SLCD_D6_PD06: J15.29(DB16) R162.2
SLCD_D7_PD07: J15.30(DB17) R164.2
SLCD_DC: R172.1 U7.C13(SLCD_DC_PWM6_PD11)
SLCD_DC_PD11: J15.8(RS) R172.2
SLCD_IOVDD: C105.1 C106.1 J15.32(IOVCC) R147.2
SLCD_LEDA: C185.2 J15.16(LED-A) U23.8(VOUT)
SLCD_LEDK: J15.17(LED1) J15.18(LED2) J15.19(LED3) J15.20(LED4) U23.4(D3) U23.5(D2) U23.6(D1)
SLCD_RDY: R174.1 U7.C14(SLCD_RDY_PWM7_PD12)
SLCD_RDY_PD12: J15.10(RD) R157.1 R174.2
SLCD_RST_PD09: J15.31(RESET) R170.2
SLCD_TE: R170.1 U7.A13(SLCD_TE_PWM4_PD09)
SLCD_VCI: C179.1 C180.1 J15.33(VCI) R148.2
SLCD_WR_BT656_PCLK: R168.1 R169.1 U7.B14(SLCD_WR_PD08)
SLCD_WR_PD08: J15.9(WR) R168.2
SOC_0V8: FB9.2 ; also on sheet 10 11 12
SOC_1V8: C174.1 C175.1 FB10.2 R185.1 U7.K2(VDDIO18_2) ; also on sheet 10 11 12
SOC_3V3: C170.1 C171.1 J4.1 R40.1 R42.2 R45.2 R46.1 R138.1 U7.J14(VDDIO1_2) U7.P9(VDDIO1_1) ; also on sheet 10 12
SOC_BT_RST_N/PIR_IoT: J14.16 R229.2 R230.2
SOC_BT_RST_PC17: R229.1 U7.B3(SSI_SLV_DT_I2S_SDTO_PC17)
SOC_PWR_EN_IoT: J9.17 ; also on sheet 10
SOC_WIFI_OOB_PC15: J14.1 U7.B4(SSI_SLV_CLK_I2S_DAC_BCLK_PC15)
SPEAK_EN: U7.B10(GPIO_PB31) ; also on sheet 13
TX+: J13.1(CON_PIN[0]) U20.9(RX-/TX-)
TX-: J13.2(CON_PIN[1]) U20.11(RX+/TX+)
TX_N0: U19.4(TRXN0) U20.6(RD+/TD+)
TX_P0: U19.3(TRXP0) U20.8(RD-/TD-)
UART1_RXD: R42.1 R48.2 U7.F16(UART1_RXD_PB24)
UART1_TXD: R45.1 R51.2 U7.F15(UART1_TXD_PB23)
UART2_RXD_PC14: R215.1 U7.C7(I2S_ADC_LRCK_PC14)
UART2_TXD_PC13: J14.12 U7.B7(I2S_ADC_BCLK_PC13)
USB_DET_IoT: C9.1 R10.1 R12.2 R188.1
USB_DM0: D2.2(CATHODE) J2.2(D-) ; also on sheet 12
USB_DP0: D1.2(CATHODE) J2.3(D+) ; also on sheet 12
VOUT: C198.1 R255.1 R259.2 U16.2(VOUT)
WIFI_IO: C114.1 J14.17 R186.1
WIFI_MSC1_CLK_PC02: J9.10 U7.A1(MSC1_CLK_PC02)
WIFI_MSC1_CMD_PC03: J9.7 R246.2 U7.C3(MSC1_CMD_PC03)
WIFI_MSC1_D0_PC04: J9.11 R247.2 U7.B2(MSC1_D0_PC04)
WIFI_MSC1_D1_PC05: J9.14 R248.2 U7.A2(MSC1_D1_PC05)
WIFI_MSC1_D2_PC06: J9.5 R249.2 U7.C2(MSC1_D2_PC06)
WIFI_MSC1_D3_PC07: J9.6 R250.2 U7.B1(MSC1_D3_PC07)
WIFI_VBAT: C111.1 C112.1 C113.1 J9.1 J9.2 ; also on sheet 10
N16605475: R6.2 U1.11(ISET1)
N16605479: R7.2 U1.12(ISET2)
N16605539: L1.1 U1.3(SW_0) U1.4(SW_1)
N16605973: R4.1 R5.1 U1.13(USB_DET)
N16607200: J1.3 R1.2
N16979467: D4.2(CATHODE) J4.4 R51.1
N16979485: D5.2(CATHODE) J4.3 R48.1
N16985653: R38.2 U7.E1(SA1_DVP_MCLK_PA15)
N16994635: R143.2 U7.E2(WAIT_PA19)
N17002165: R191.2 U19.26(CRS/CRS_DV)
N17002179: R195.2 U19.9(RXD[0])
N17002181: R198.2 U19.10(RXD[1])
N17002261: R209.1 U19.30(NC)
N17002291: R204.2 U19.32(XTAL_OUT)
N17002321: R190.2 U19.15(TXC)
N17002359: C118.1 C119.1 U19.2(AVDDL_REG)
N17002395: C149.1 C150.1 U19.29(DVDDL_REG)
N17002469: R201.2 U19.28(RXER)
N17002544: R194.1 U19.1(PBIAS)
N17002574: C156.2 U20.7(CT2)
N17002587: D17.1 R221.2 U20.10(CT3) U20.13(MCT) U20.15(CT4)
N17002598: C155.2 U20.5(CT)
N17002608: C154.2 U20.2(CT1)
N17002683: J13.11(CON_PIN[10]) R211.1
N17002690: J13.13(CON_PIN[12]) R217.1
N17002738: C157.2 R221.1
N17006161: R98.1 R139.1 R246.1 R247.1 R248.1 R249.1 R250.1
N17009042: Q4.2(EMITTER) R92.2
N17009044: Q5.3(DRAIN) R113.2 R115.2
N17009046: Q5.1(GATE) R114.1
N17009089: C121.1 C122.1 R111.2 U15.1(VIN)
N17009287: Q6.3(DRAIN) R268.2
N17009319: Q7.3(DRAIN) R269.2
N17009402: C201.1 R258.1 R261.1 R262.2 U24.10
N17009422: R253.1 R261.2 R263.2
N17009484: C199.1 R255.2 U24.12
N17009506: C199.2 C200.1 R260.1 R264.2 U24.13
N17009512: C197.1 C200.2 R260.2 U24.14
N17009562: C202.1 R264.1
N17009566: C197.2 R256.2
N17009576: C195.1 R254.1 R256.1 U24.9
N17009610: C195.2 R254.2 R257.1 U24.3 U24.6 U24.8
N17009693: C203.1 R263.1 R266.2 U24.5
N17009695: C194.1 R227.1 R253.2 U24.2
N17009885: C188.1 C189.1 C190.1 C191.1 C192.1 C193.1 R252.2 U16.1(VCC)
N17009958: C128.1 C187.1 R228.2 R252.1
N17058437: R39.1 U7.H15(MSC0_CLK_PB04)
N17123098: C36.1 R49.1 U9.2(CELL)
N17123136: R53.1 U9.6(QSTRT)
N17123180: C45.1 R50.1 U9.3(VDD)
N17123378: R181.2 R182.2 U7.C11(SMB1_SDA_UART3_TXD_PB25)
N17123417: R183.2 R184.2 U7.C10(SMB1_SCK_UART3_RXD_PB26)
N17217380: C183.2 U23.10(C1+)
N17217382: C183.1 U23.11(C1-)
N17217384: C182.1 U23.12(C2-)
N17217386: C182.2 U23.9(C2+)
N17217517: R214.1 U23.1(ISET)
N17297664: Q5.2(SOURCE) R226.2

Not connected (* = marked no-connect by the designer): J2 4(ID)*; J13 4(CON_PIN[3])* 5(CON_PIN[4])* 7(CON_PIN[6])* 8(CON_PIN[7])* 15(NC1)* 16(NC2)*; J15 11(NC1)* 12(X+)* 13(Y-)* 14(X-)* 15(Y+)* 21(NC2)*; U7 A7(SMB1_SDA_PC19)* C8(SMB1_SCK_PC20)* F2(NC_2)* G3(NC_1)* P14(RX_DV)* R13(LED0)* R14(RXD3)* R15(LED1)* R16(AVDDL_REG)* T13(PHY_RST)* T14(DVDD1V2OUT)* T15(RBIAS)* T16(TD_P)* T17(RD_P)* U15(EN_DLDO)* U16(TD_N)* U17(RD_N)*; U9 9(EP)*; U15 4(BP/FB)*; U19 11(RXD[2]/INT_N)* 13(RXC)* 18(TXD[2])* 19(TXD[3])* 27(COL)*; U20 4(NC1)* 12(NC2)*; U23 2(NC2)* 3(NC1)*

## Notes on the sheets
sheet 1
- SLCD_BT656_OUT
- Note：The 0Ω resistance in         is used for measuring power consumption
  and can be removed in the product board.
- NC
- NC
- SLCD_BackLight_Power
- NC
- NC
- NC
- NC
- NC
- NC
- NC
- EN1&EN2
  0 : BACK LIGHT SHUTDOWN
  1 : BACK LIGHT ENABLE
  PWM : DIMMING
- I(CH)*3=30mA(Max)*3
- INGENIC SEMICONDUCTOR CO.,LTD
sheet 2
- ETH_PHY
- NC
- LED MODE
- NC
- NC
- RMII MODE
- NC
- REF_CLK Output RMII2
- NC
- NC
- PHY Address : 00000b
- NC
- Note: R209 Compatible with JL1101
- NC
- INGENIC SEMICONDUCTOR CO.,LTD
sheet 3
- WIFI_MOUDLE(IoT)
- NC
- NC
- NC
- NC
- NC
- WIFI Board
- NC
- INGENIC SEMICONDUCTOR CO.,LTD
sheet 4
- T41_INTERFACE02
- NC
- NOR FLASH
- INGENIC SEMICONDUCTOR CO.,LTD
sheet 5
- T41_INTERFACE01
- NC
- This part is NC
  for T41ZN/T41ZL
- NC
- GAS GAUGE
- NC
- INGENIC SEMICONDUCTOR CO.,LTD
- I2C Address: 0b1100010
sheet 6
- PIR_LDR
- PIR Power
- 默认高电平
- 电压范围：0---1.8V
- The resistance value is adjusted according to the photodiode
- Select analog or digital PIR
- Analog PIR
- NC
- Digital PIR
- NC
- PIR_L/H:
- Interrupt input
- PIR_MCU:
- Analog signal input
- PIR_L/H:
- MCU Output, sensitivity can be adjusted dynamically.
  The voltage dividing resistance (R153  R156)can be adjusted according to the demand.
  Optional Features
- INGENIC SEMICONDUCTOR CO.,LTD
sheet 7
- RD_T41_INDUS
- INGENIC
- Schematic Revision  1.1
- Title
- Page
- COVER
- 1
- SYSTEM-ARCHITECTURE
- 2
- POWER-SUPPLY_BAT_USB
- 3
- POWER-SUPPLY
- 4
- T41-POWER
- 5
- T41_SYS_APeripheral
- 6
- T41_INTERFACE01
- 7
- T41_INTERFACE02
- 8
- SD_AUDIO_EMMC
- 9
- SLCD_BT656
- 10
- MIPI_DVP_CAMERA
- 11
- WIFI_MOUDLE
- 12
- ETH_PHY
- 13
- PIR_LDR
- 14
- KEY_LED_RTC_BOOT
- 15
- REVISION-HISTORY
- 16
- INGENIC SEMICONDUCTOR CO.,LTD
sheet 8
- Battery
- GAS GAUGE
- SMB1
- SD/EMMC
- MSC0
- CONSOLE
- UART1
- BAT_ALRT_N
- MIPI
- BAT_ADC
- NOR FLASH 1
- SMBO
- SENSOR
- RESET MCLK
- UART0_TXD
- NOR FLASH 2
- download
- UART0_RXD
- UART0
- IRCUT
- AIP
- LED_R
- MIC
- GPIO_05
- MEAS2
- GPIO_10
- GPIO_08
- LED
- SPK_EN
- MSC1_CMD  CLK  D0
- GPIO13--18
- SPK
- T41
- HPOUT
- MCU_INT_SOC
- KEY
- GPIO_12
- GPIO_01
- KEY
- WIFI_MOUDLE
  (ATBM6441)
- IRLED
- IR
- BT UART
- PIR_MCU
- Digital
- GPIO_02
- MEAS1
- ADC0
- 32K
- PIR
- H-LDR
- GPIO_03
- GPIO_00
- GPIO_6
- GPIO_7
- BOOTSEL0
- PIR_3V3
- BOOT
- 24M
- SOC_PWR_EN
- VCC_3V3
- CHARG_DET_N
- SOC_3V3
- SOC_1V8
- SOC_1V5
- SOC_0V8
- USB_DET
- USB
- DP DM
- LDO
- USB_5V
- Battery
- SOC POWER
- SWITCH
- CHARGE
- WIFI_VBAT
- INGENIC SEMICONDUCTOR CO.,LTD
sheet 9
- POWER-SUPPLY_BAT_USB
- POWER SW
- NC
- For debug
- Charger:
    1. MP2625b
    2. ETA6003
    ...
- NC
- Li-ion/Li-Pol battery
- NC
- NC
- Battery have NTC : TP2 connect to the NTC pin of Battary
  Battery have not NTC : NTC pin pull-down
- INGENIC SEMICONDUCTOR CO.,LTD
